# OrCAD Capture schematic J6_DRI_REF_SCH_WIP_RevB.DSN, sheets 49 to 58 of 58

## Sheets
49 SH52 - BD POWER 3V3 SWITCHED: size B; rev: A
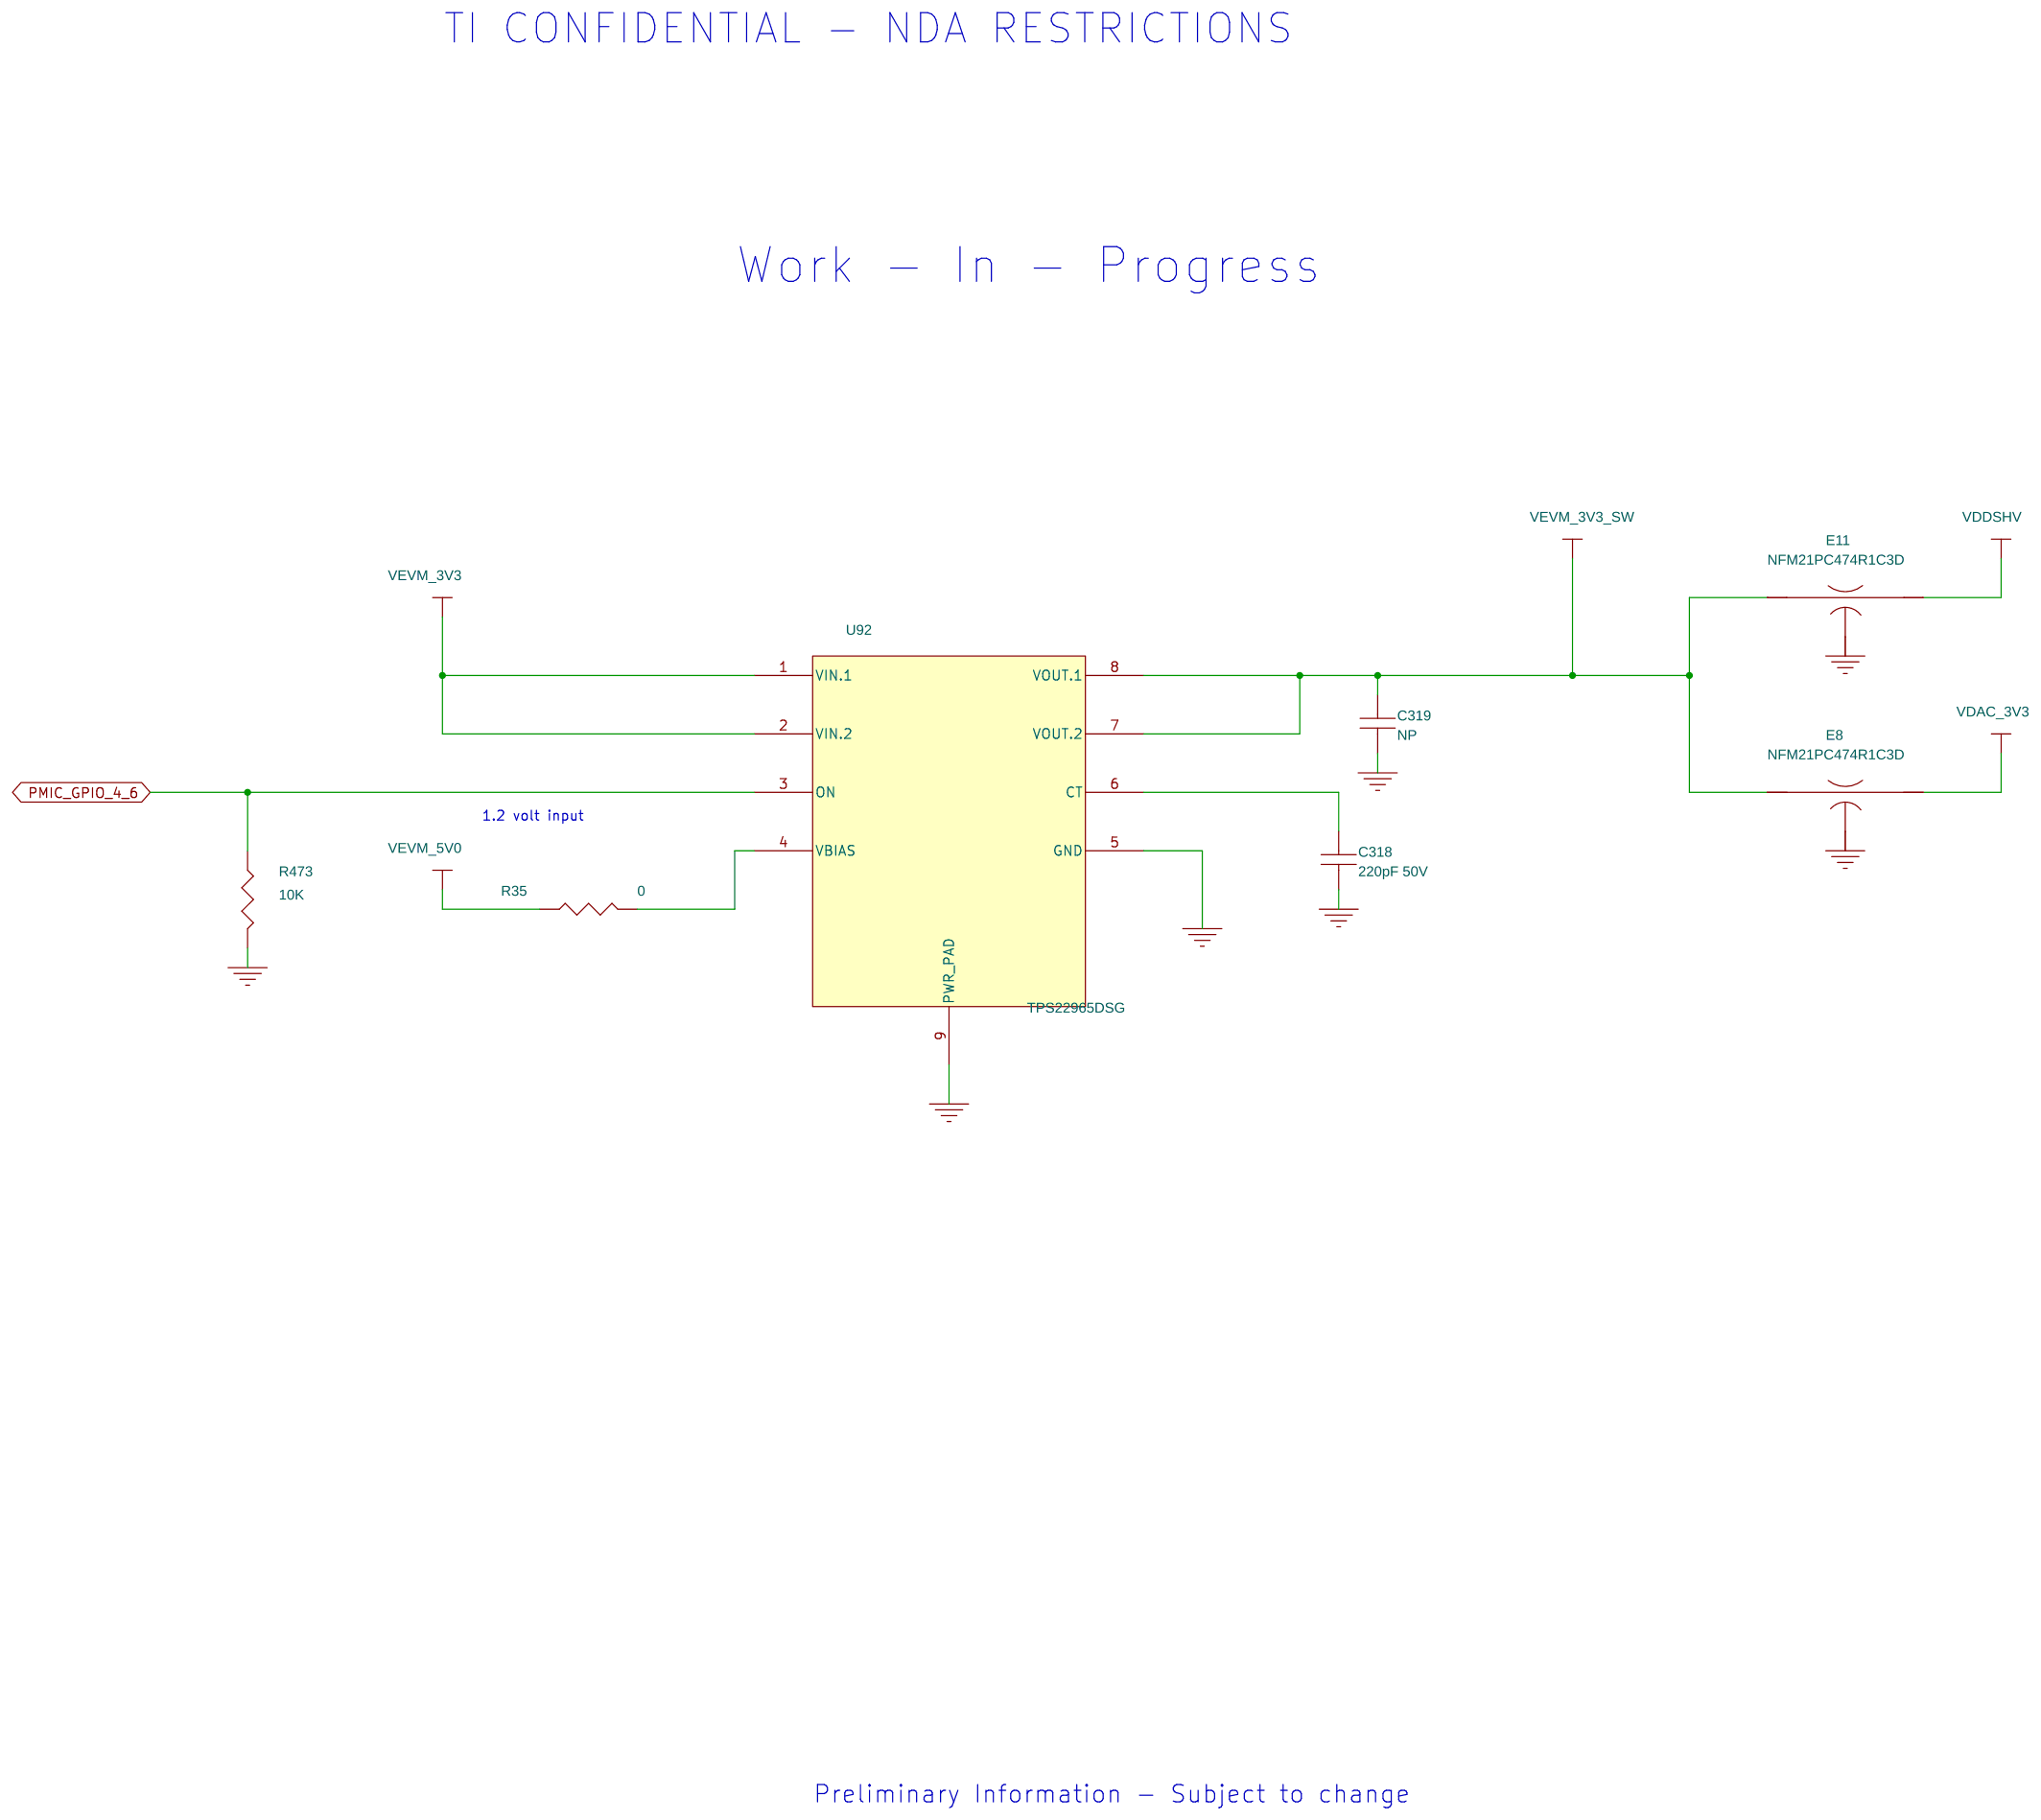
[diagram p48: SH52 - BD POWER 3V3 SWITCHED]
50 SH53 - BD POWER VTT DDR3 TERM: size B; rev: A
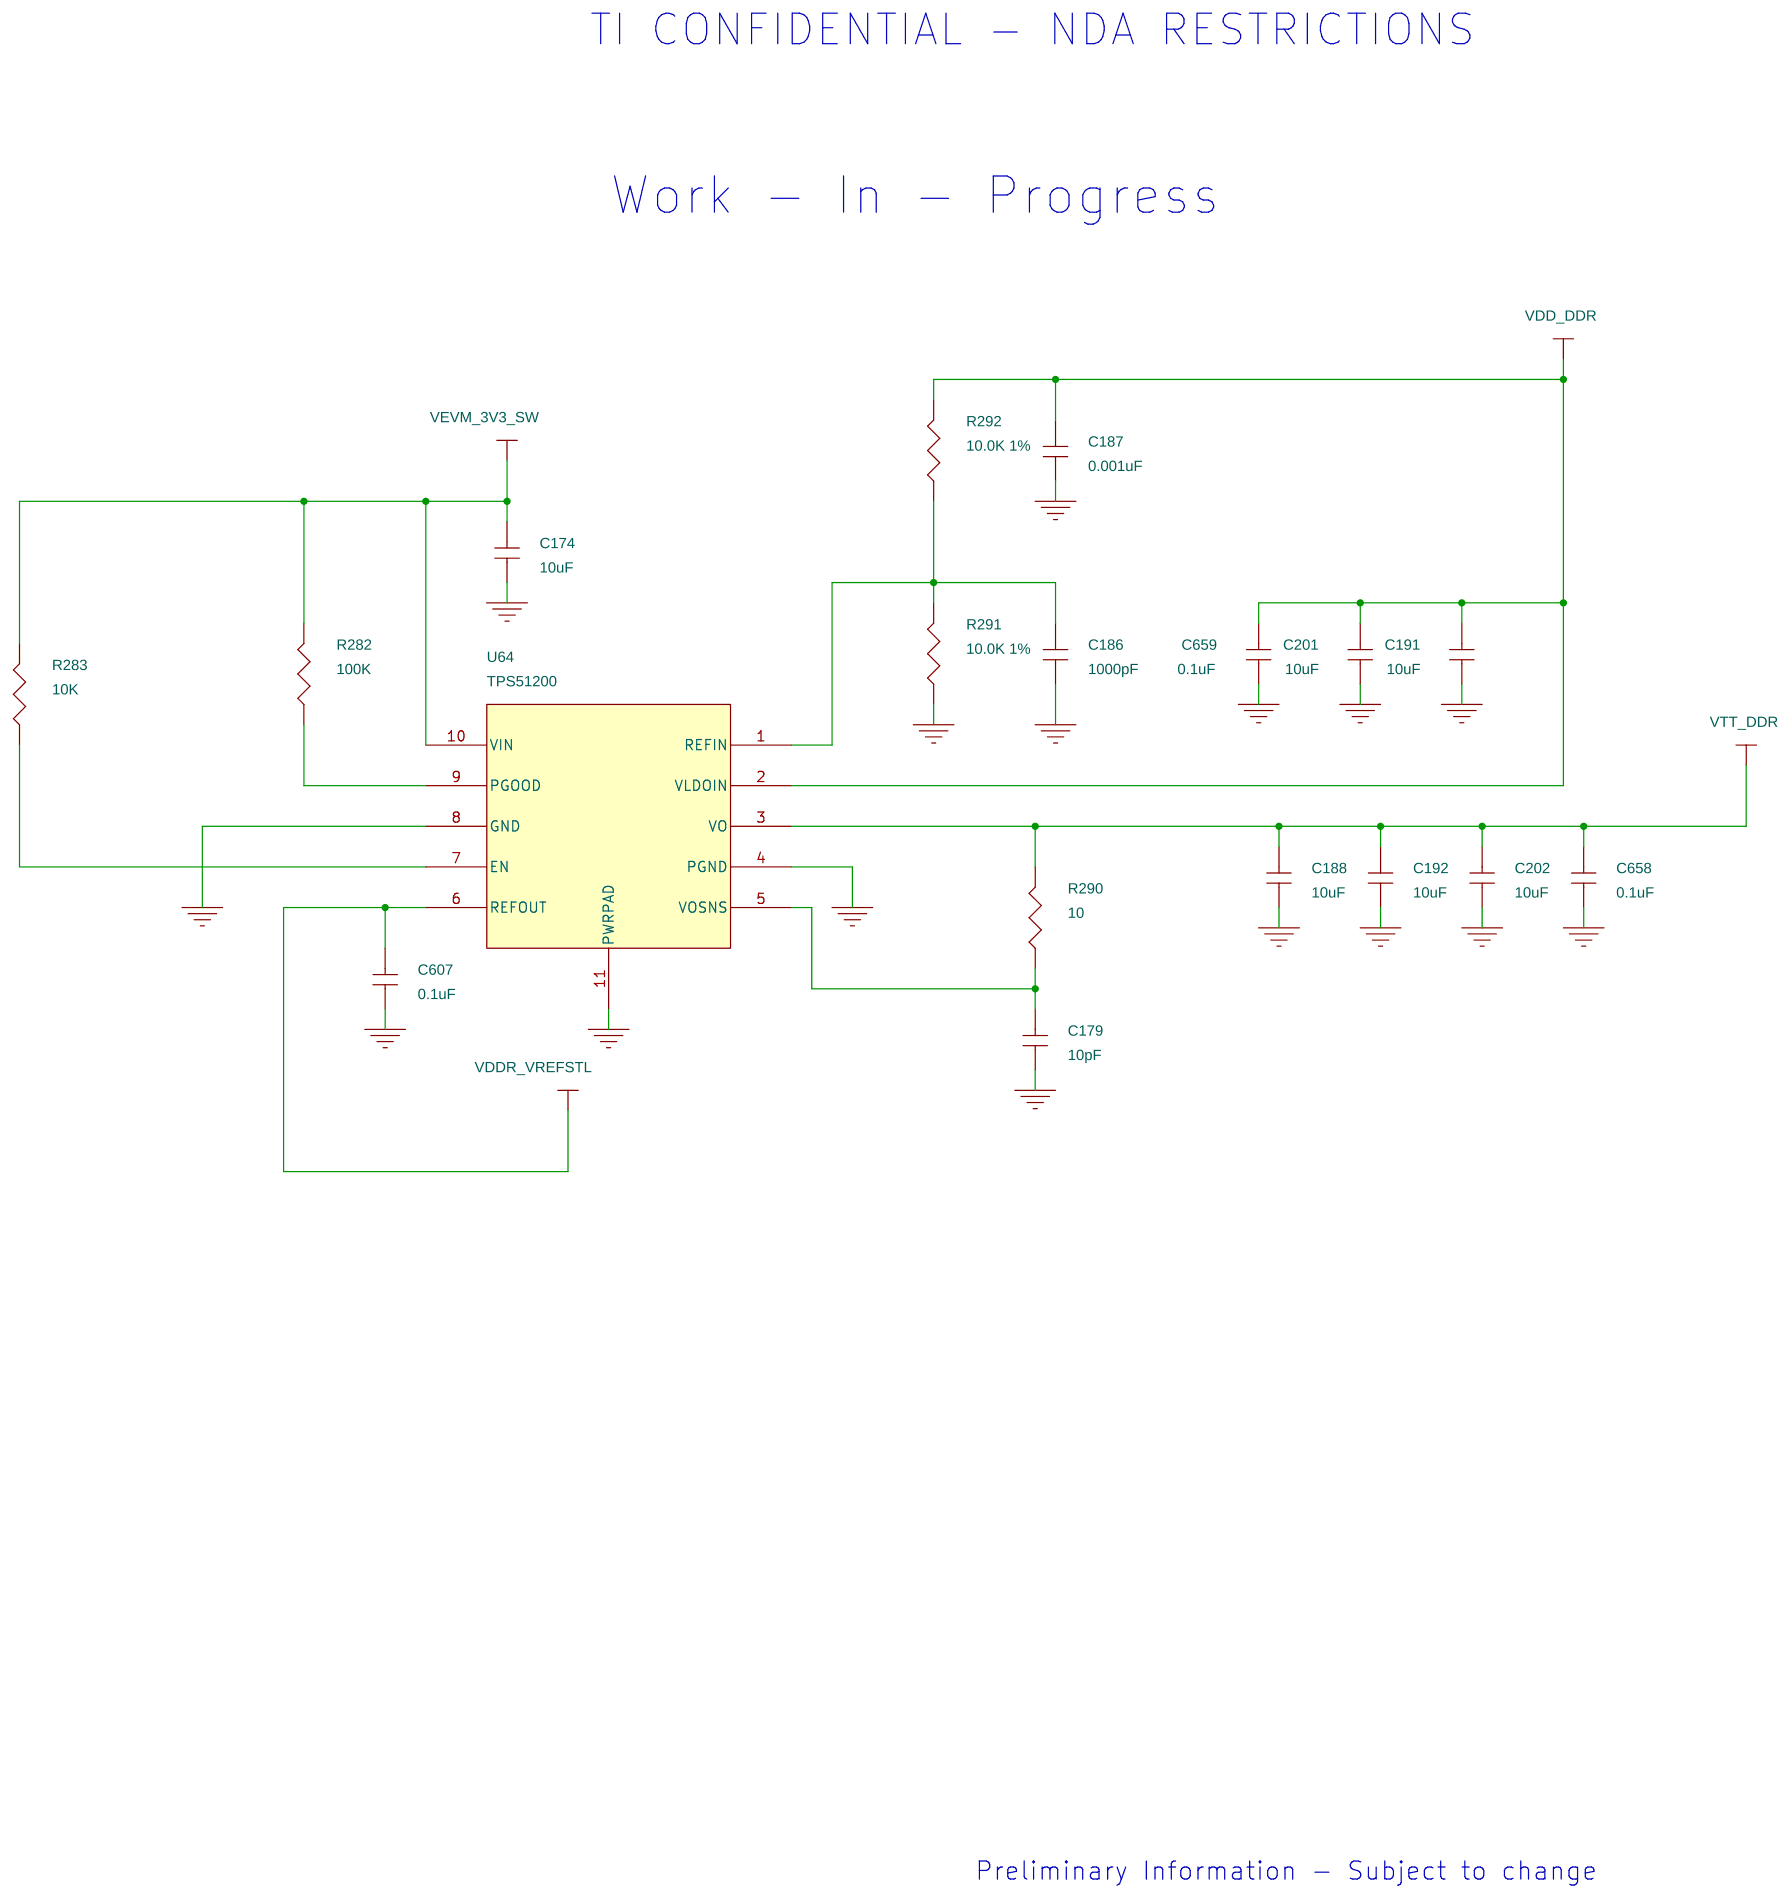
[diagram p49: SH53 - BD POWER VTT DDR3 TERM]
51 SH54 - BD POWER 1V35 DDR3 CORE: size B; rev: A
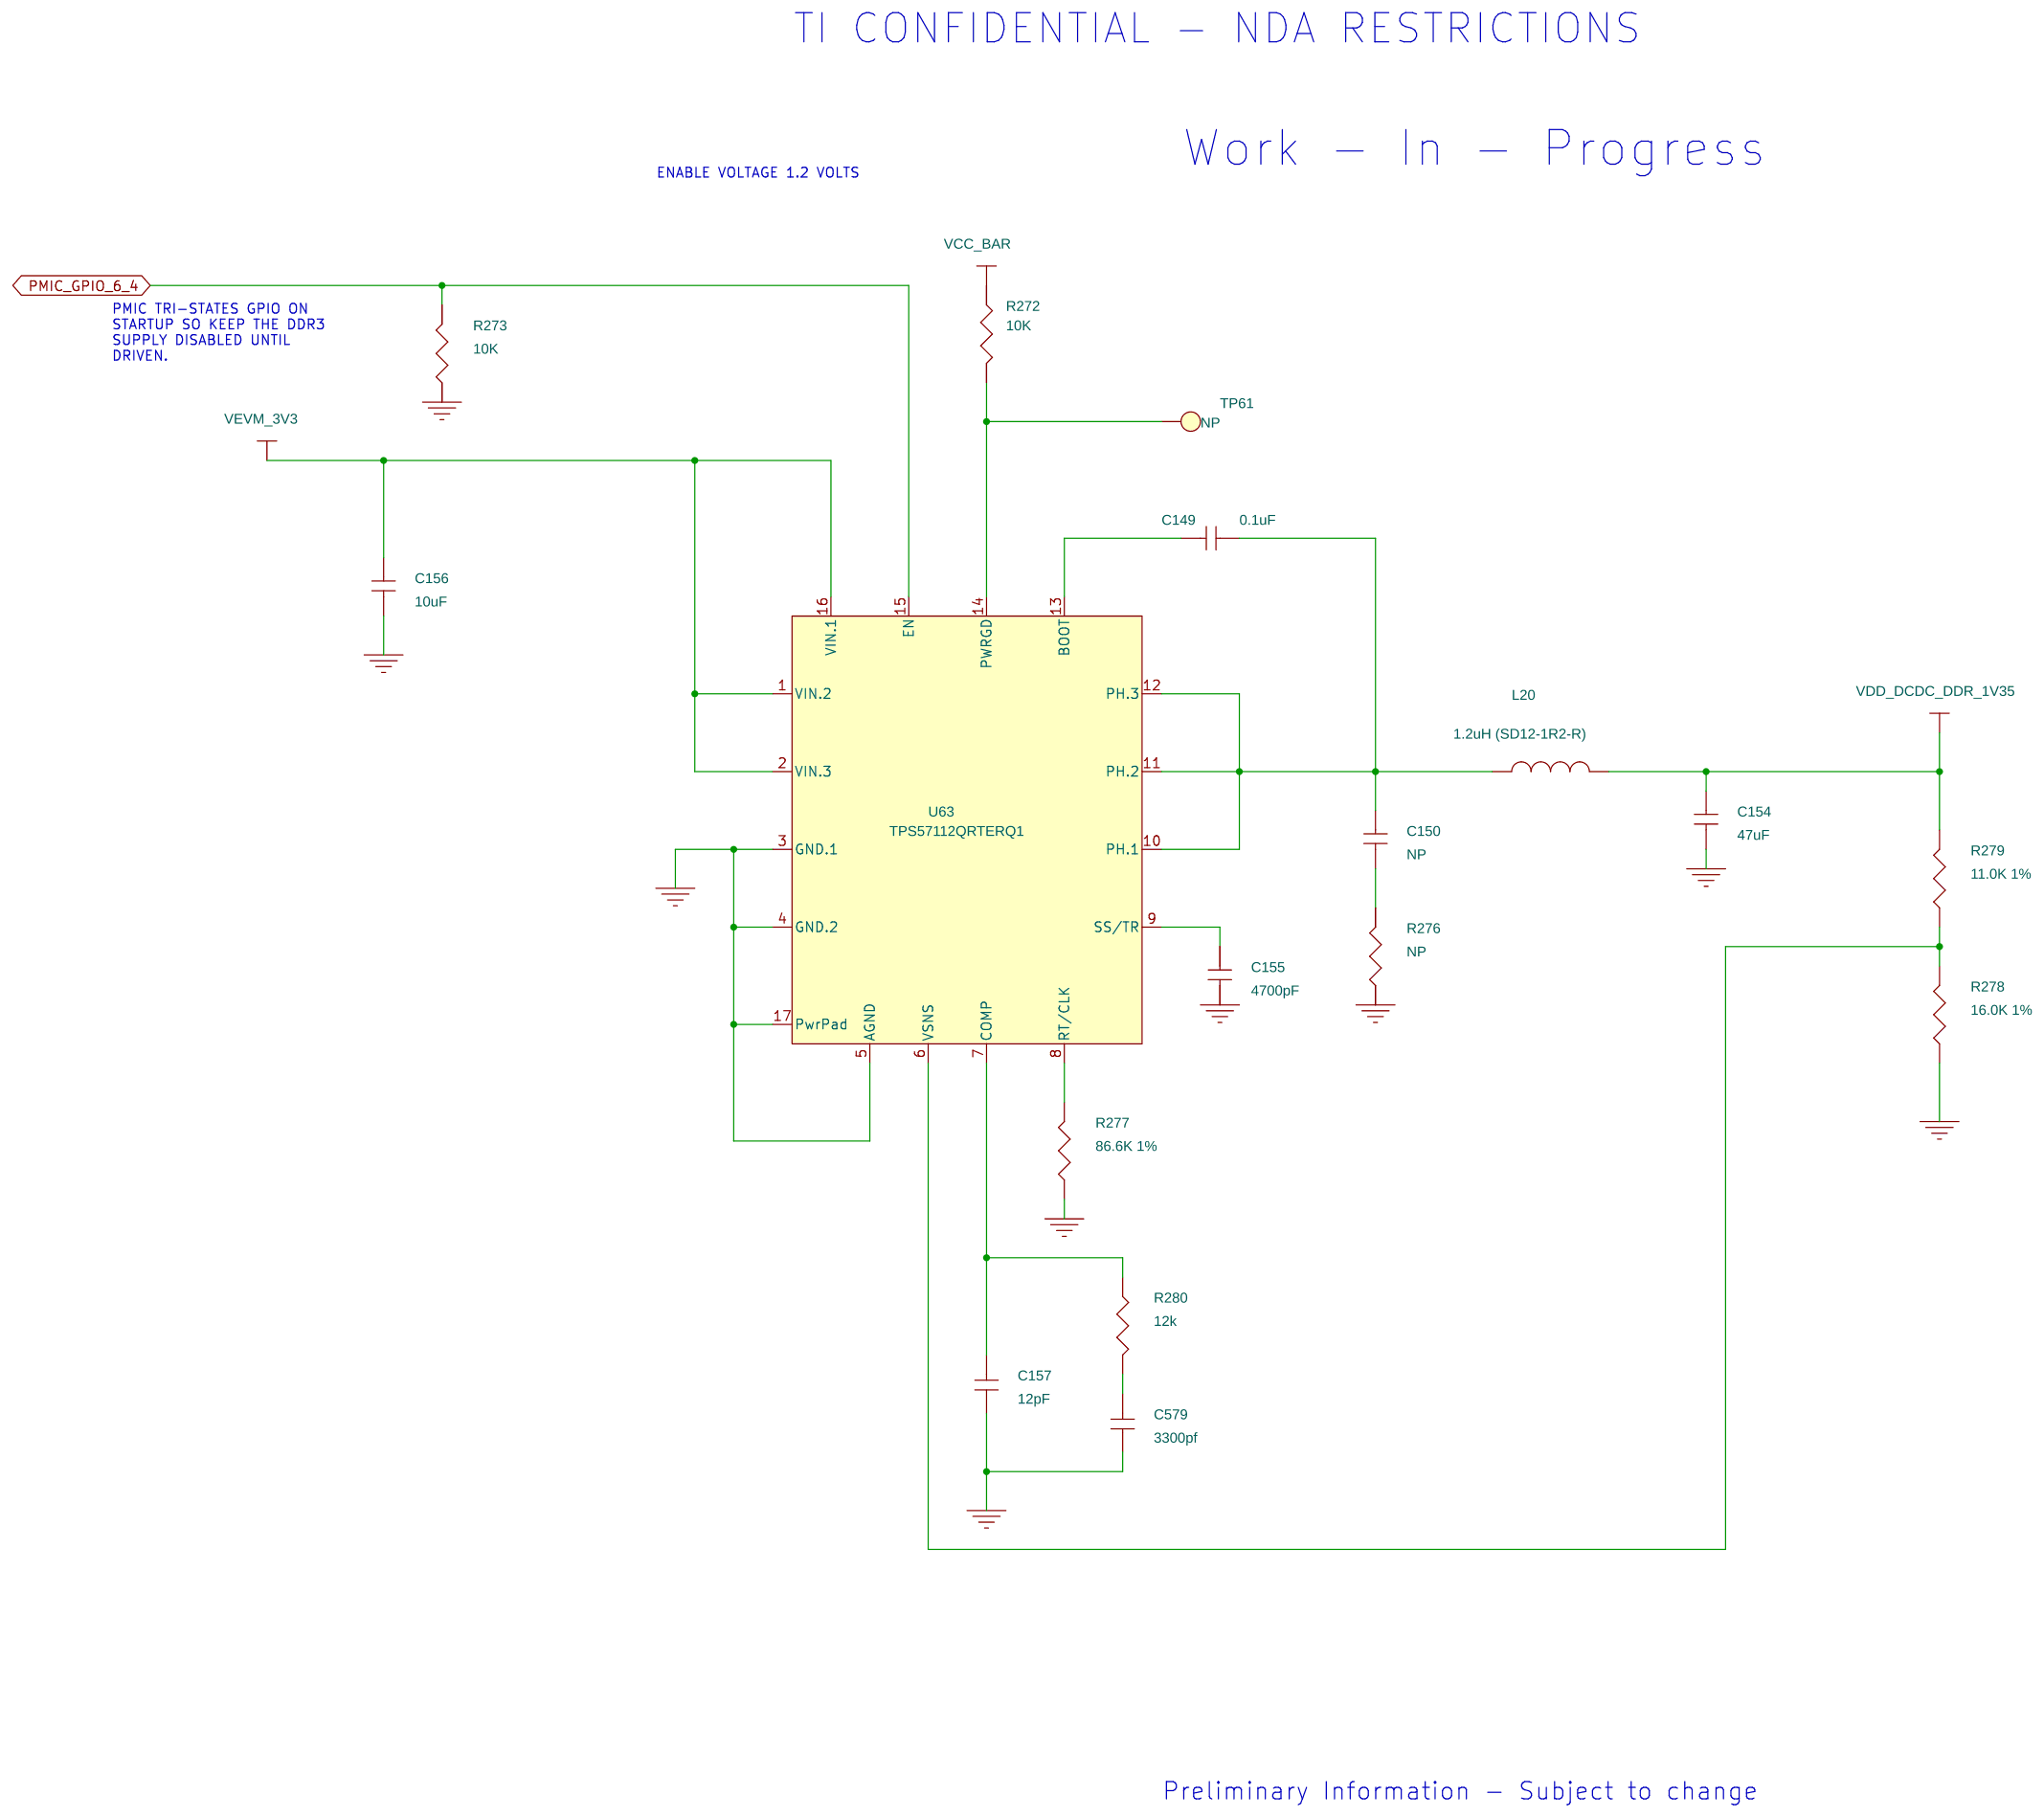
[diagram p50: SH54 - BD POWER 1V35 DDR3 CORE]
52 SH55 - BD EEPROM TEMP IPOD: size B; rev: A
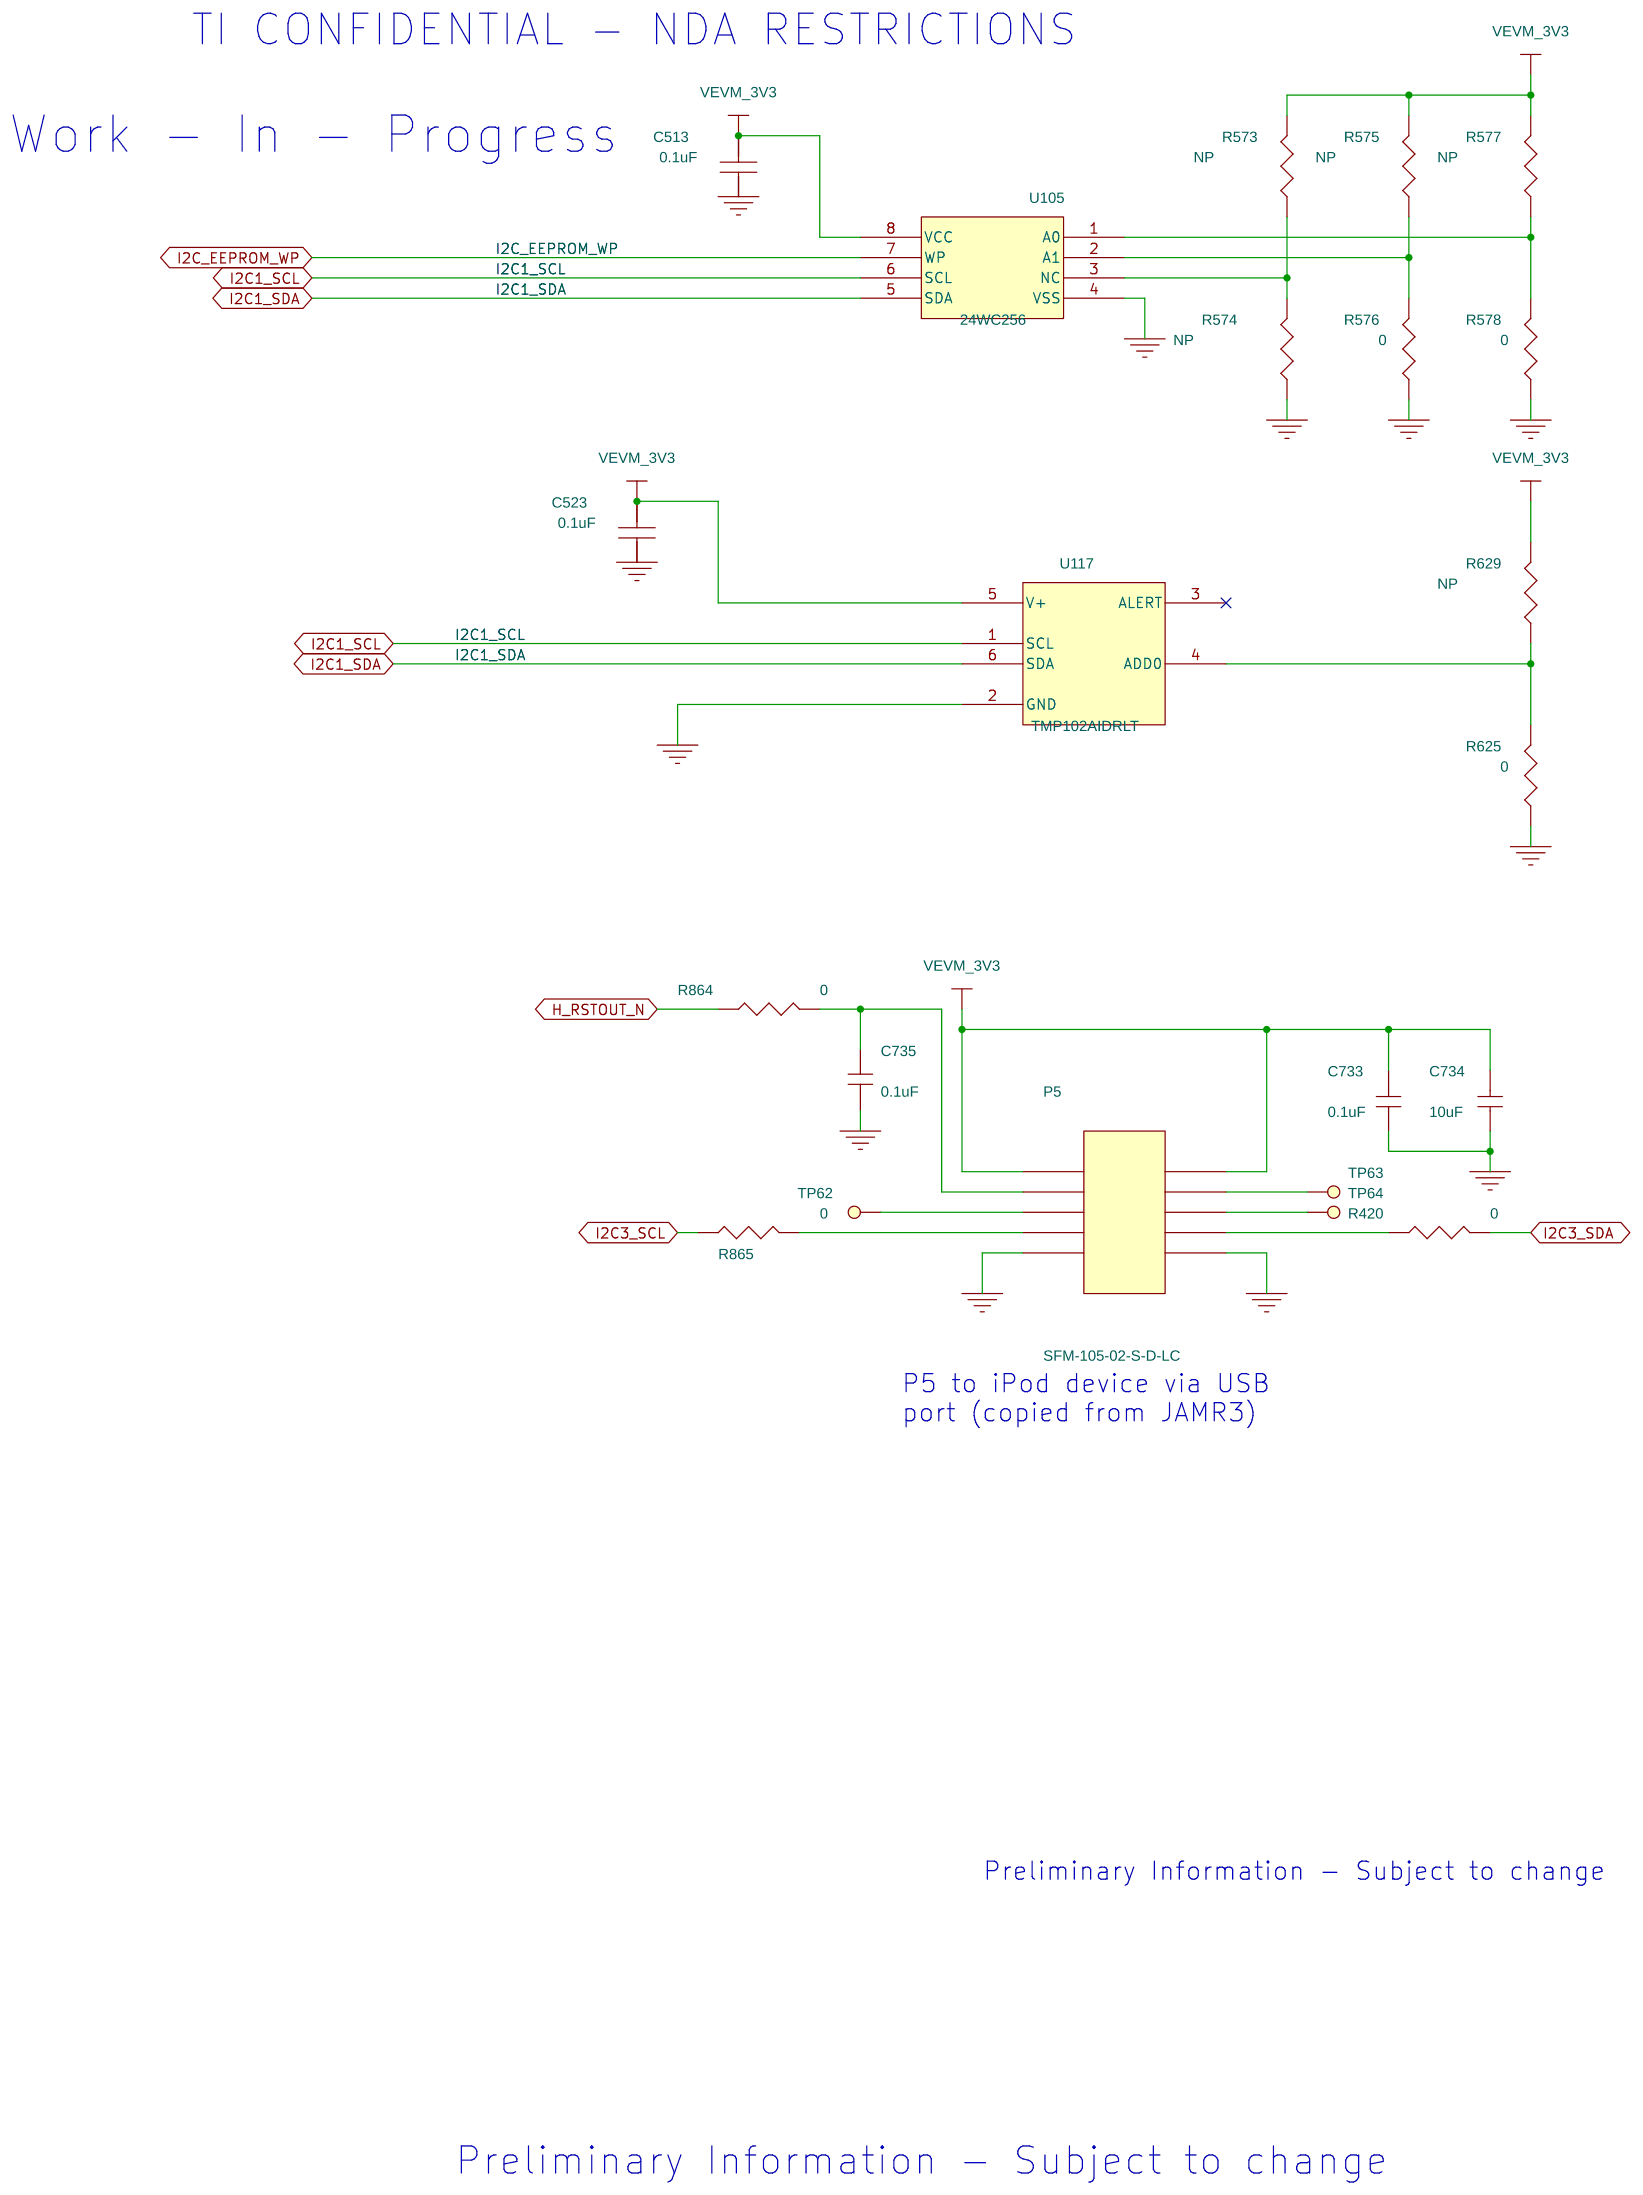
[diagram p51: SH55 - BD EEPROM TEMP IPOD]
53 SH90 - PCB Design Notes: rev: A
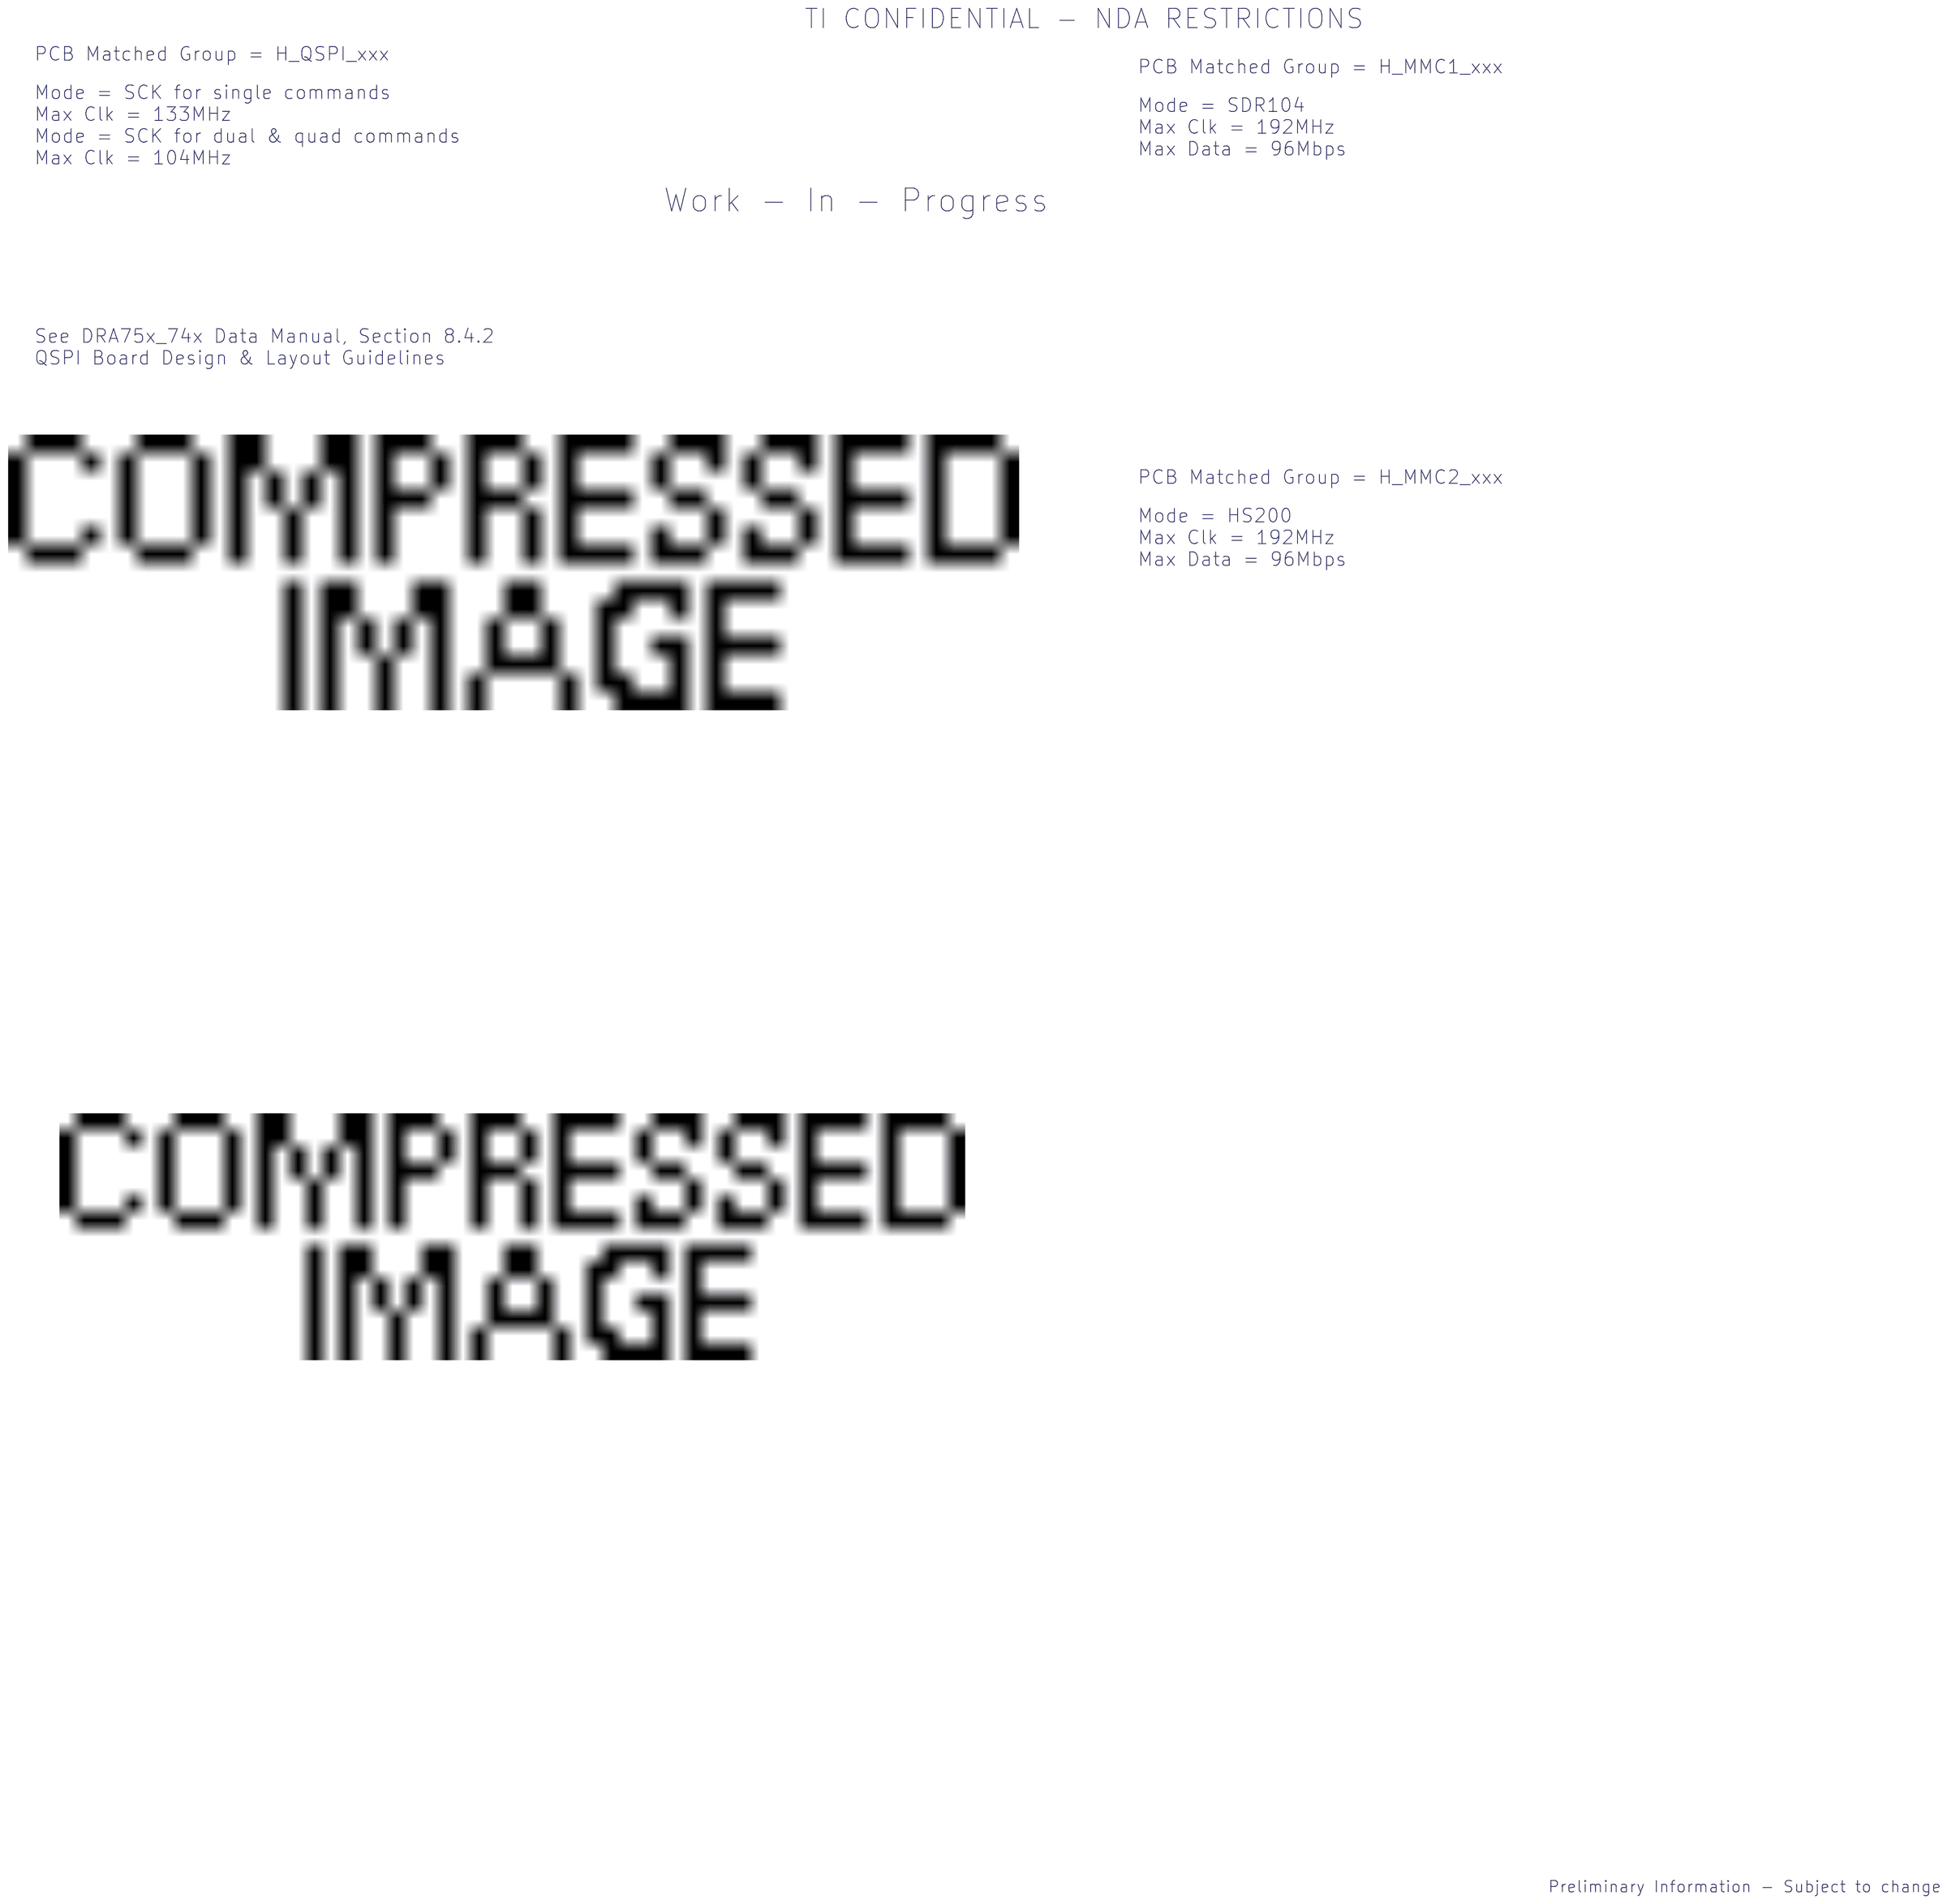
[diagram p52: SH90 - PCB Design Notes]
54 SH99 - REV HISTORY: rev: A
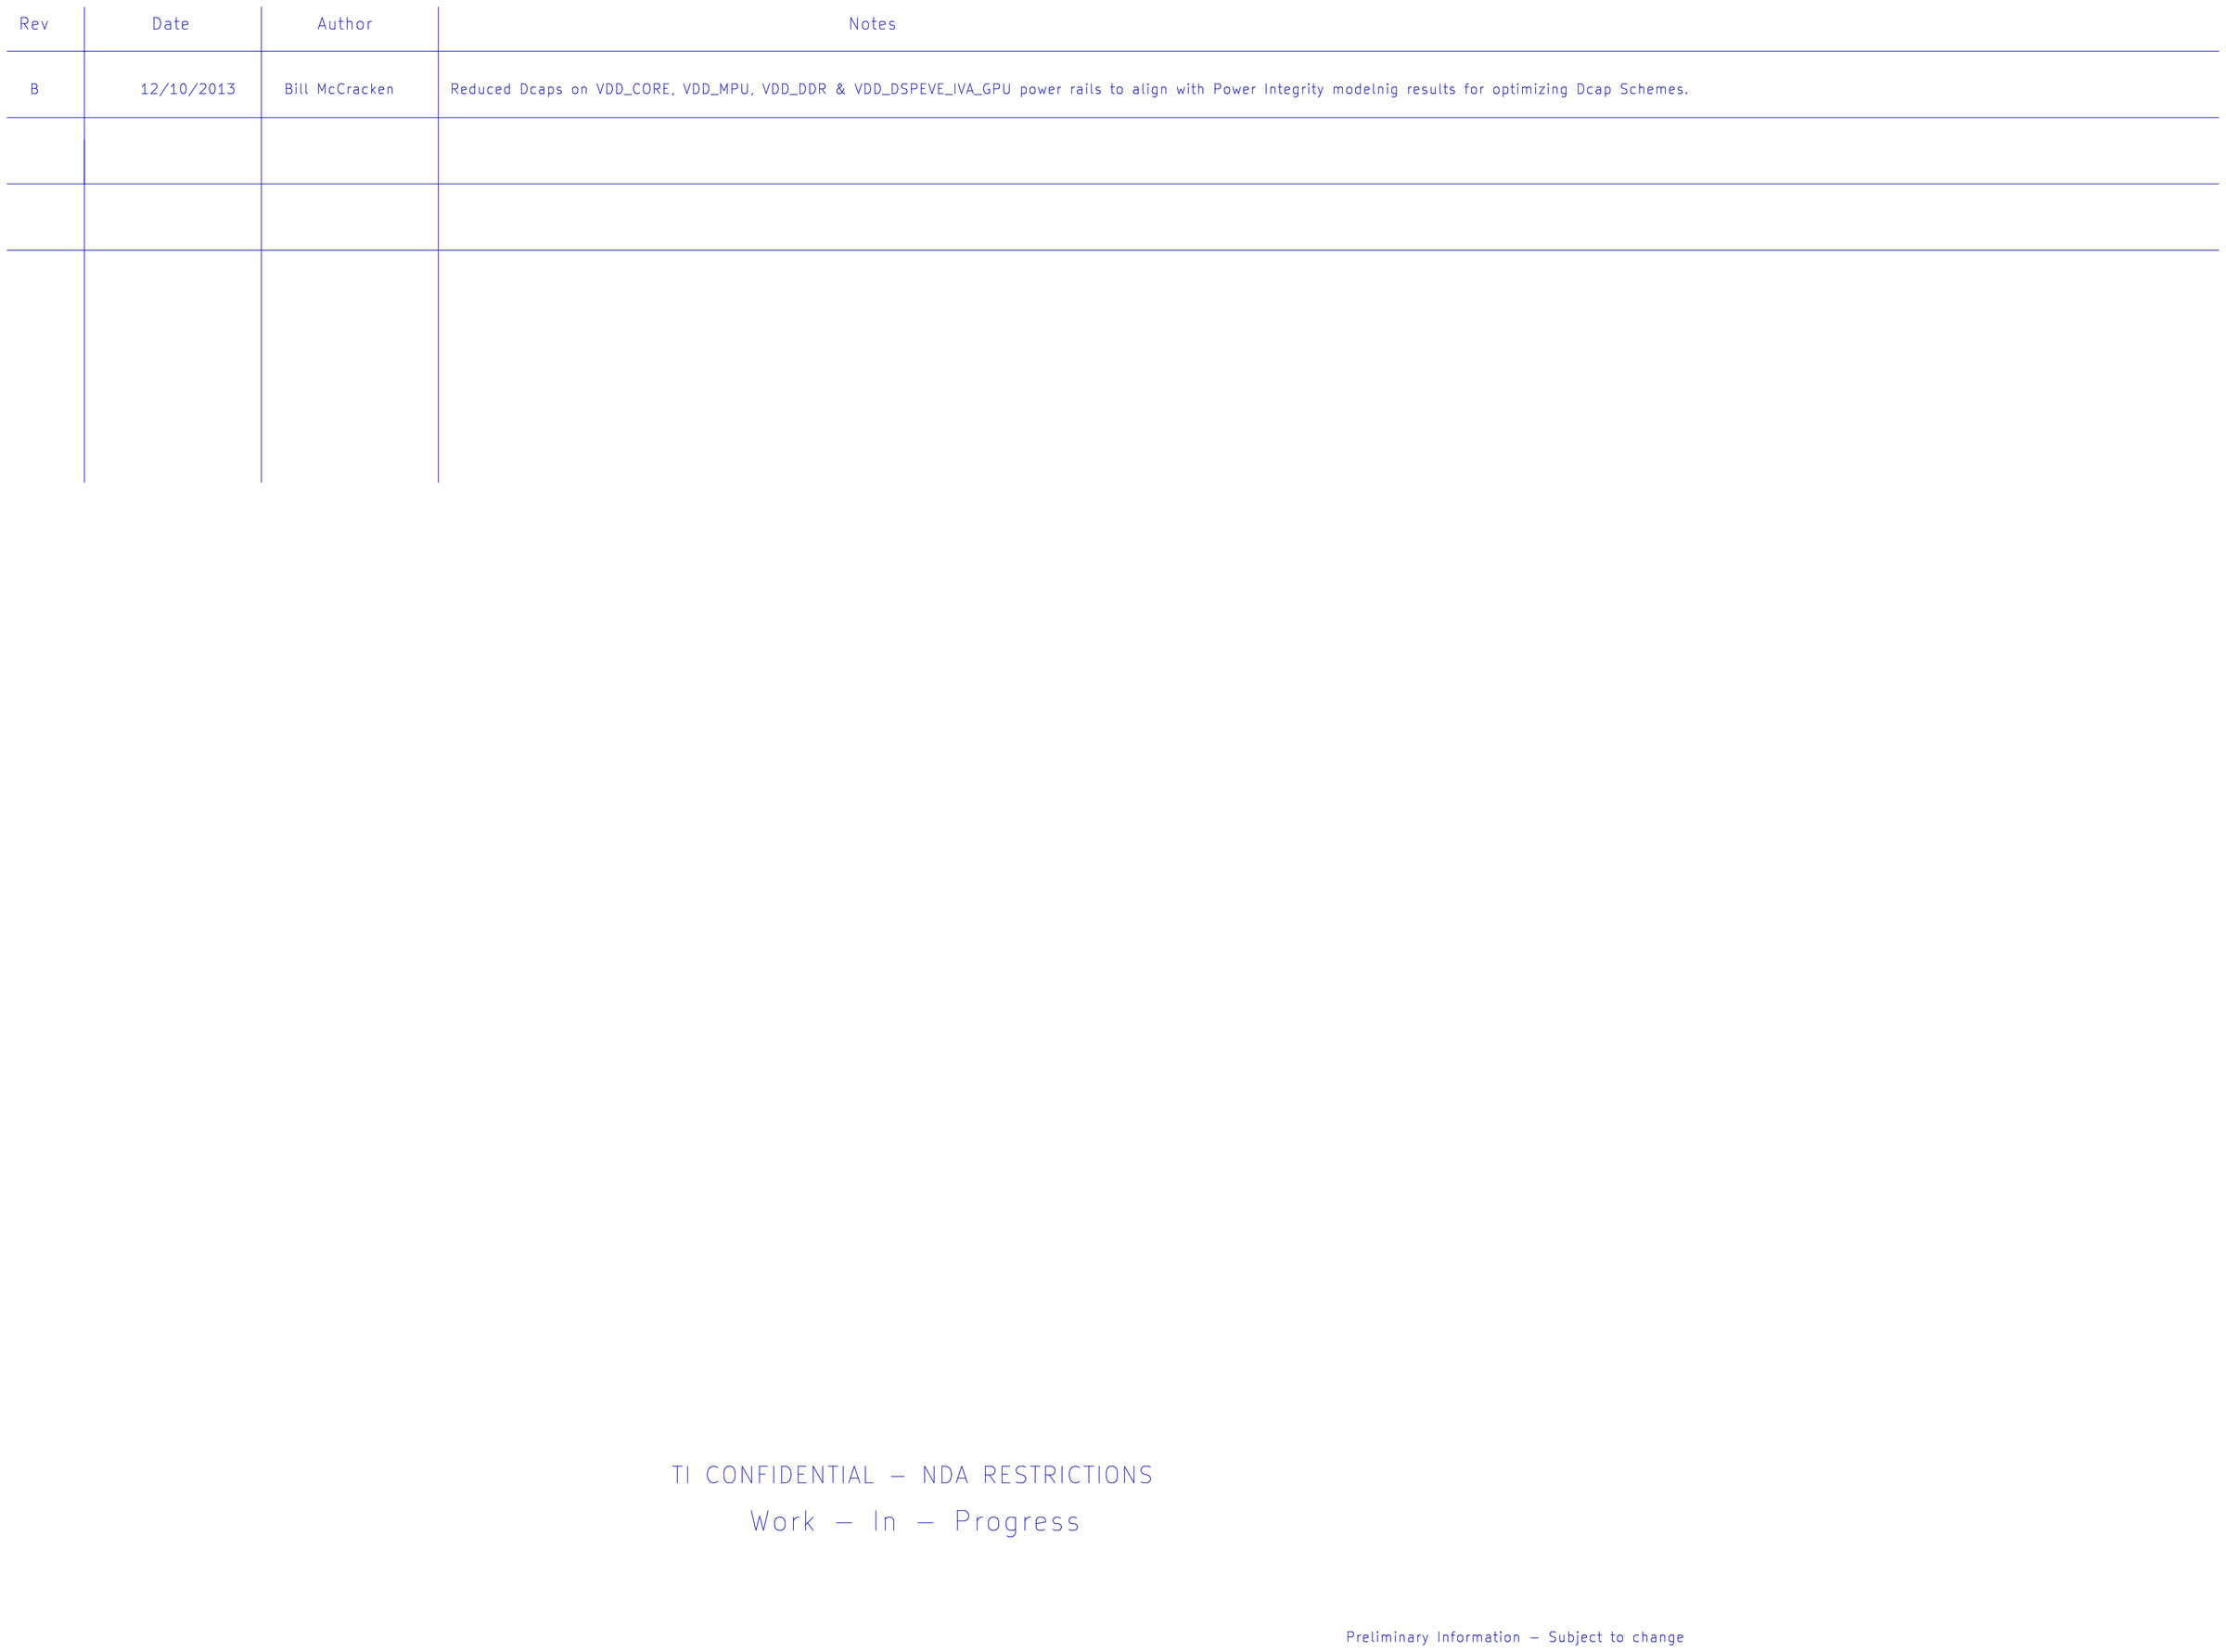
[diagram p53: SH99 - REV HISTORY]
55 SH39 - CAN/LIN: size B; rev: A
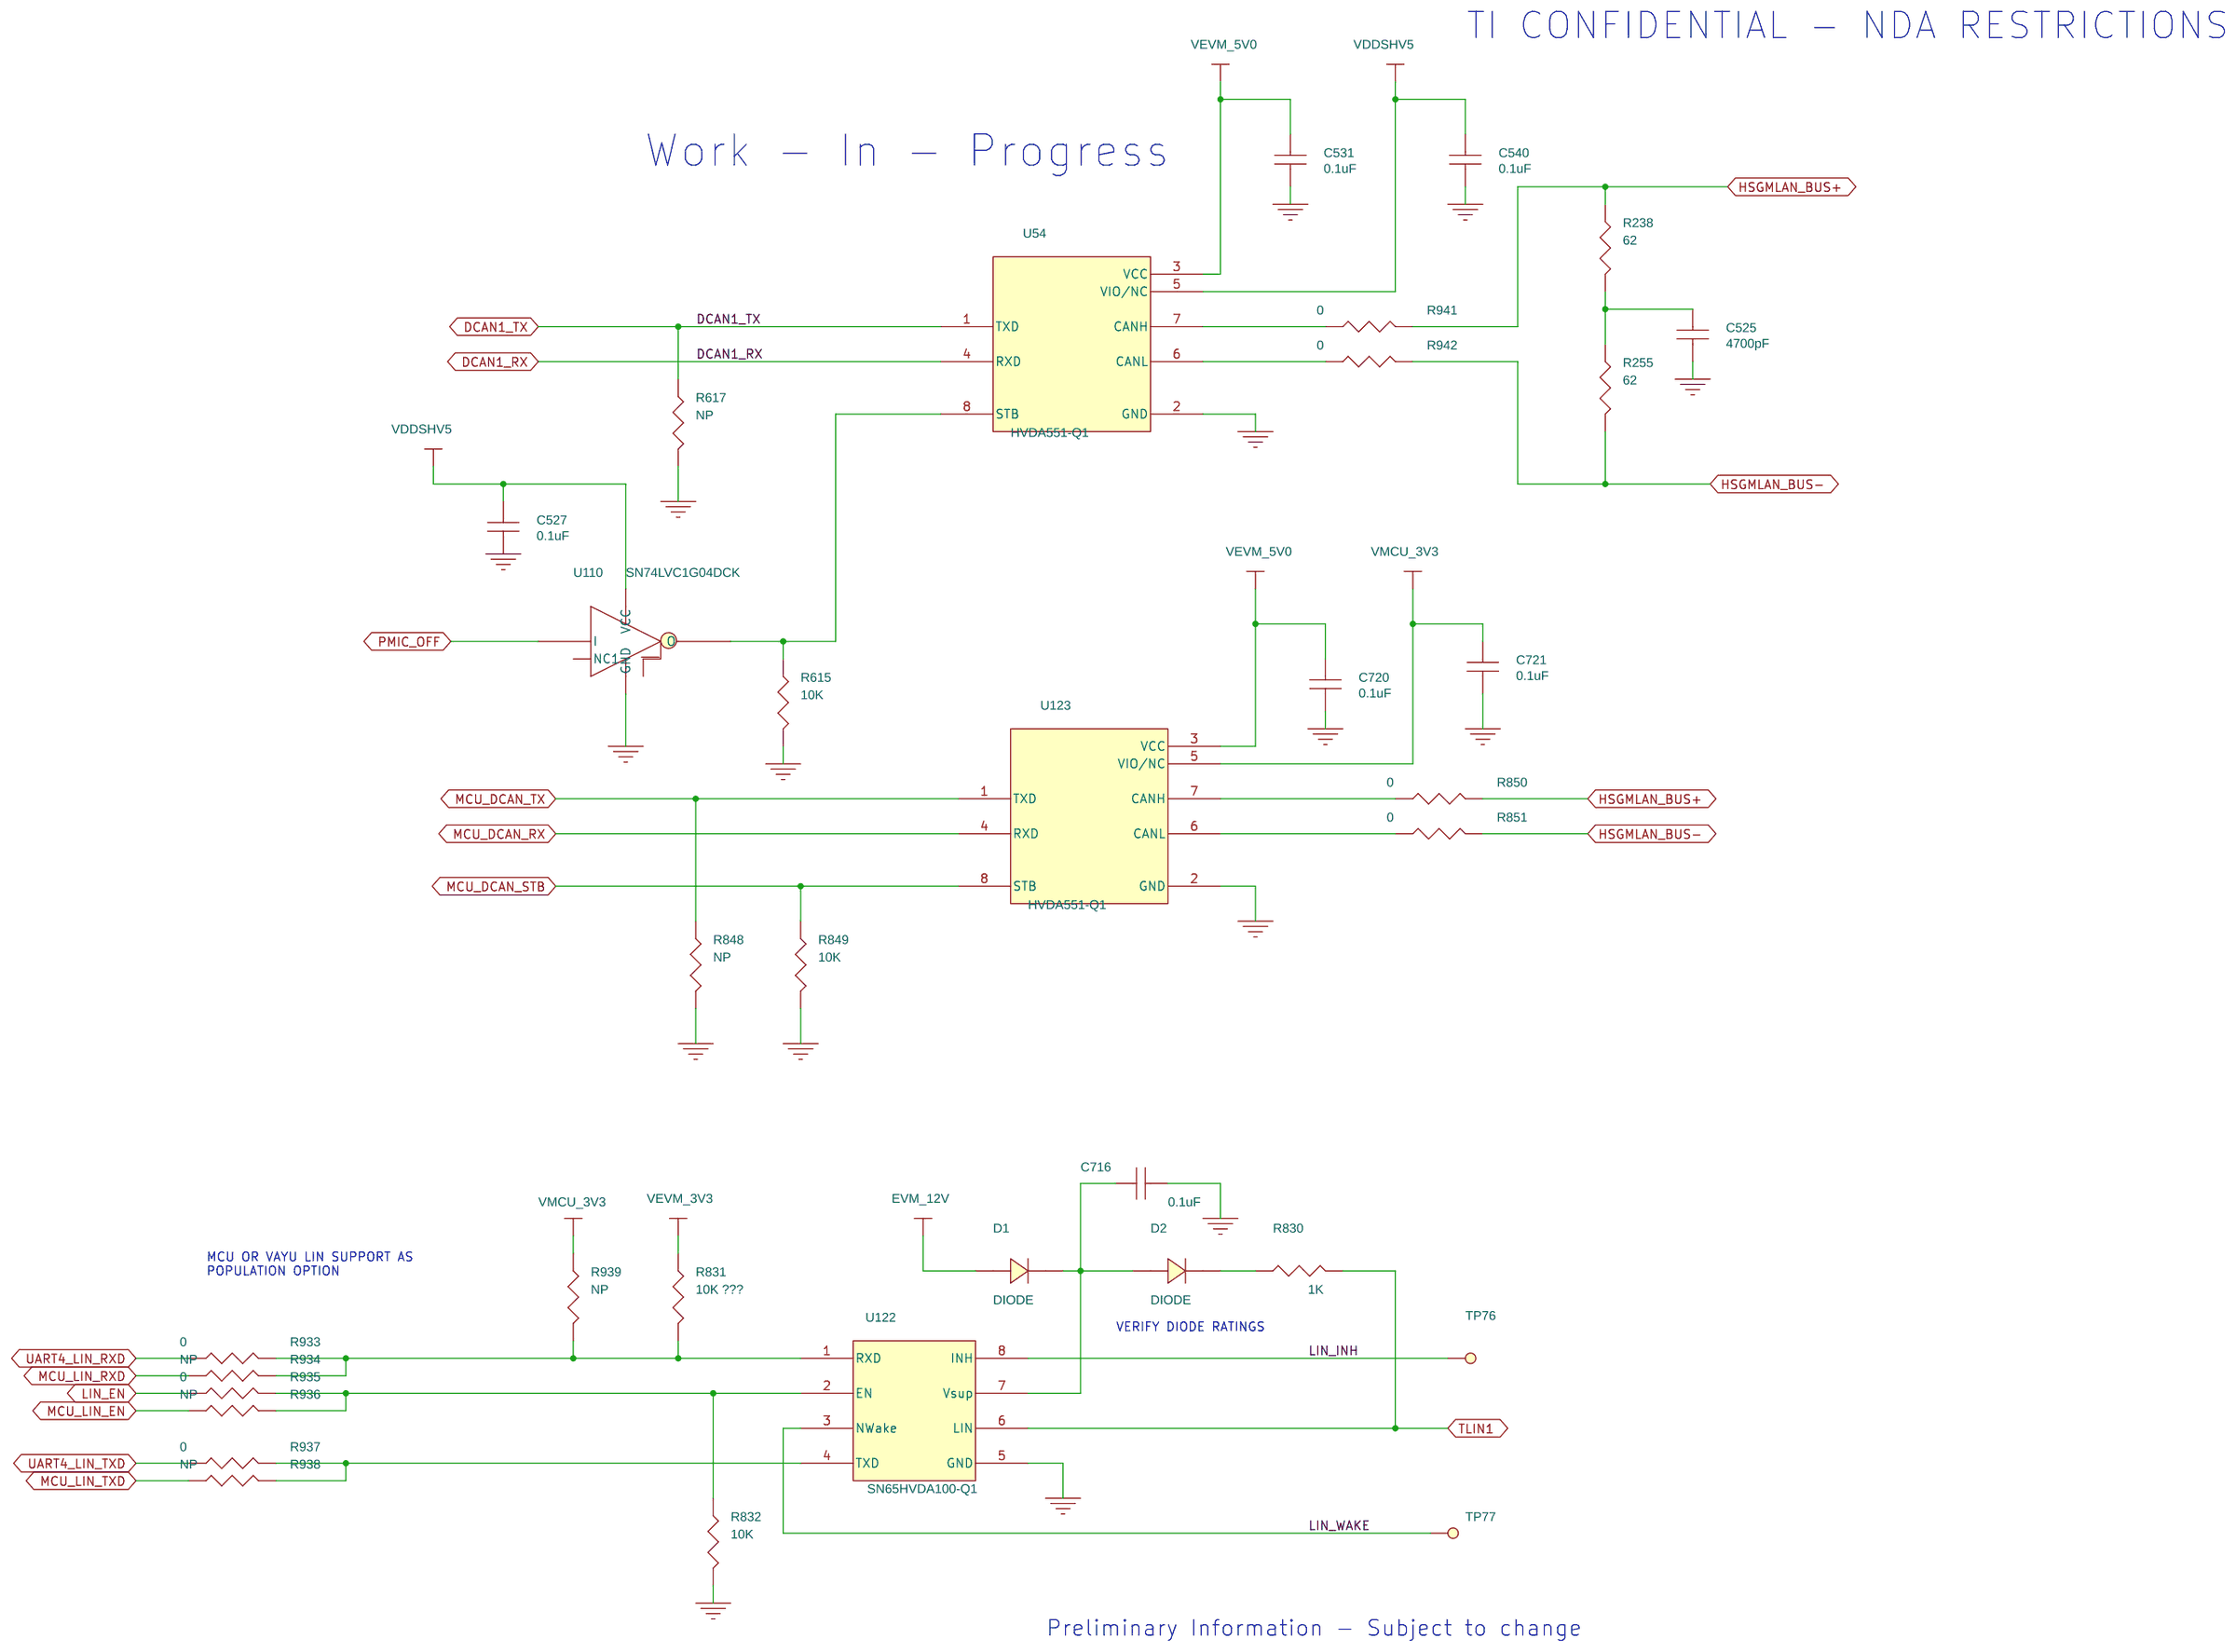
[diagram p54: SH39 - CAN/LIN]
56 SH03 - VAYU SERIAL I/O: size B; rev: A
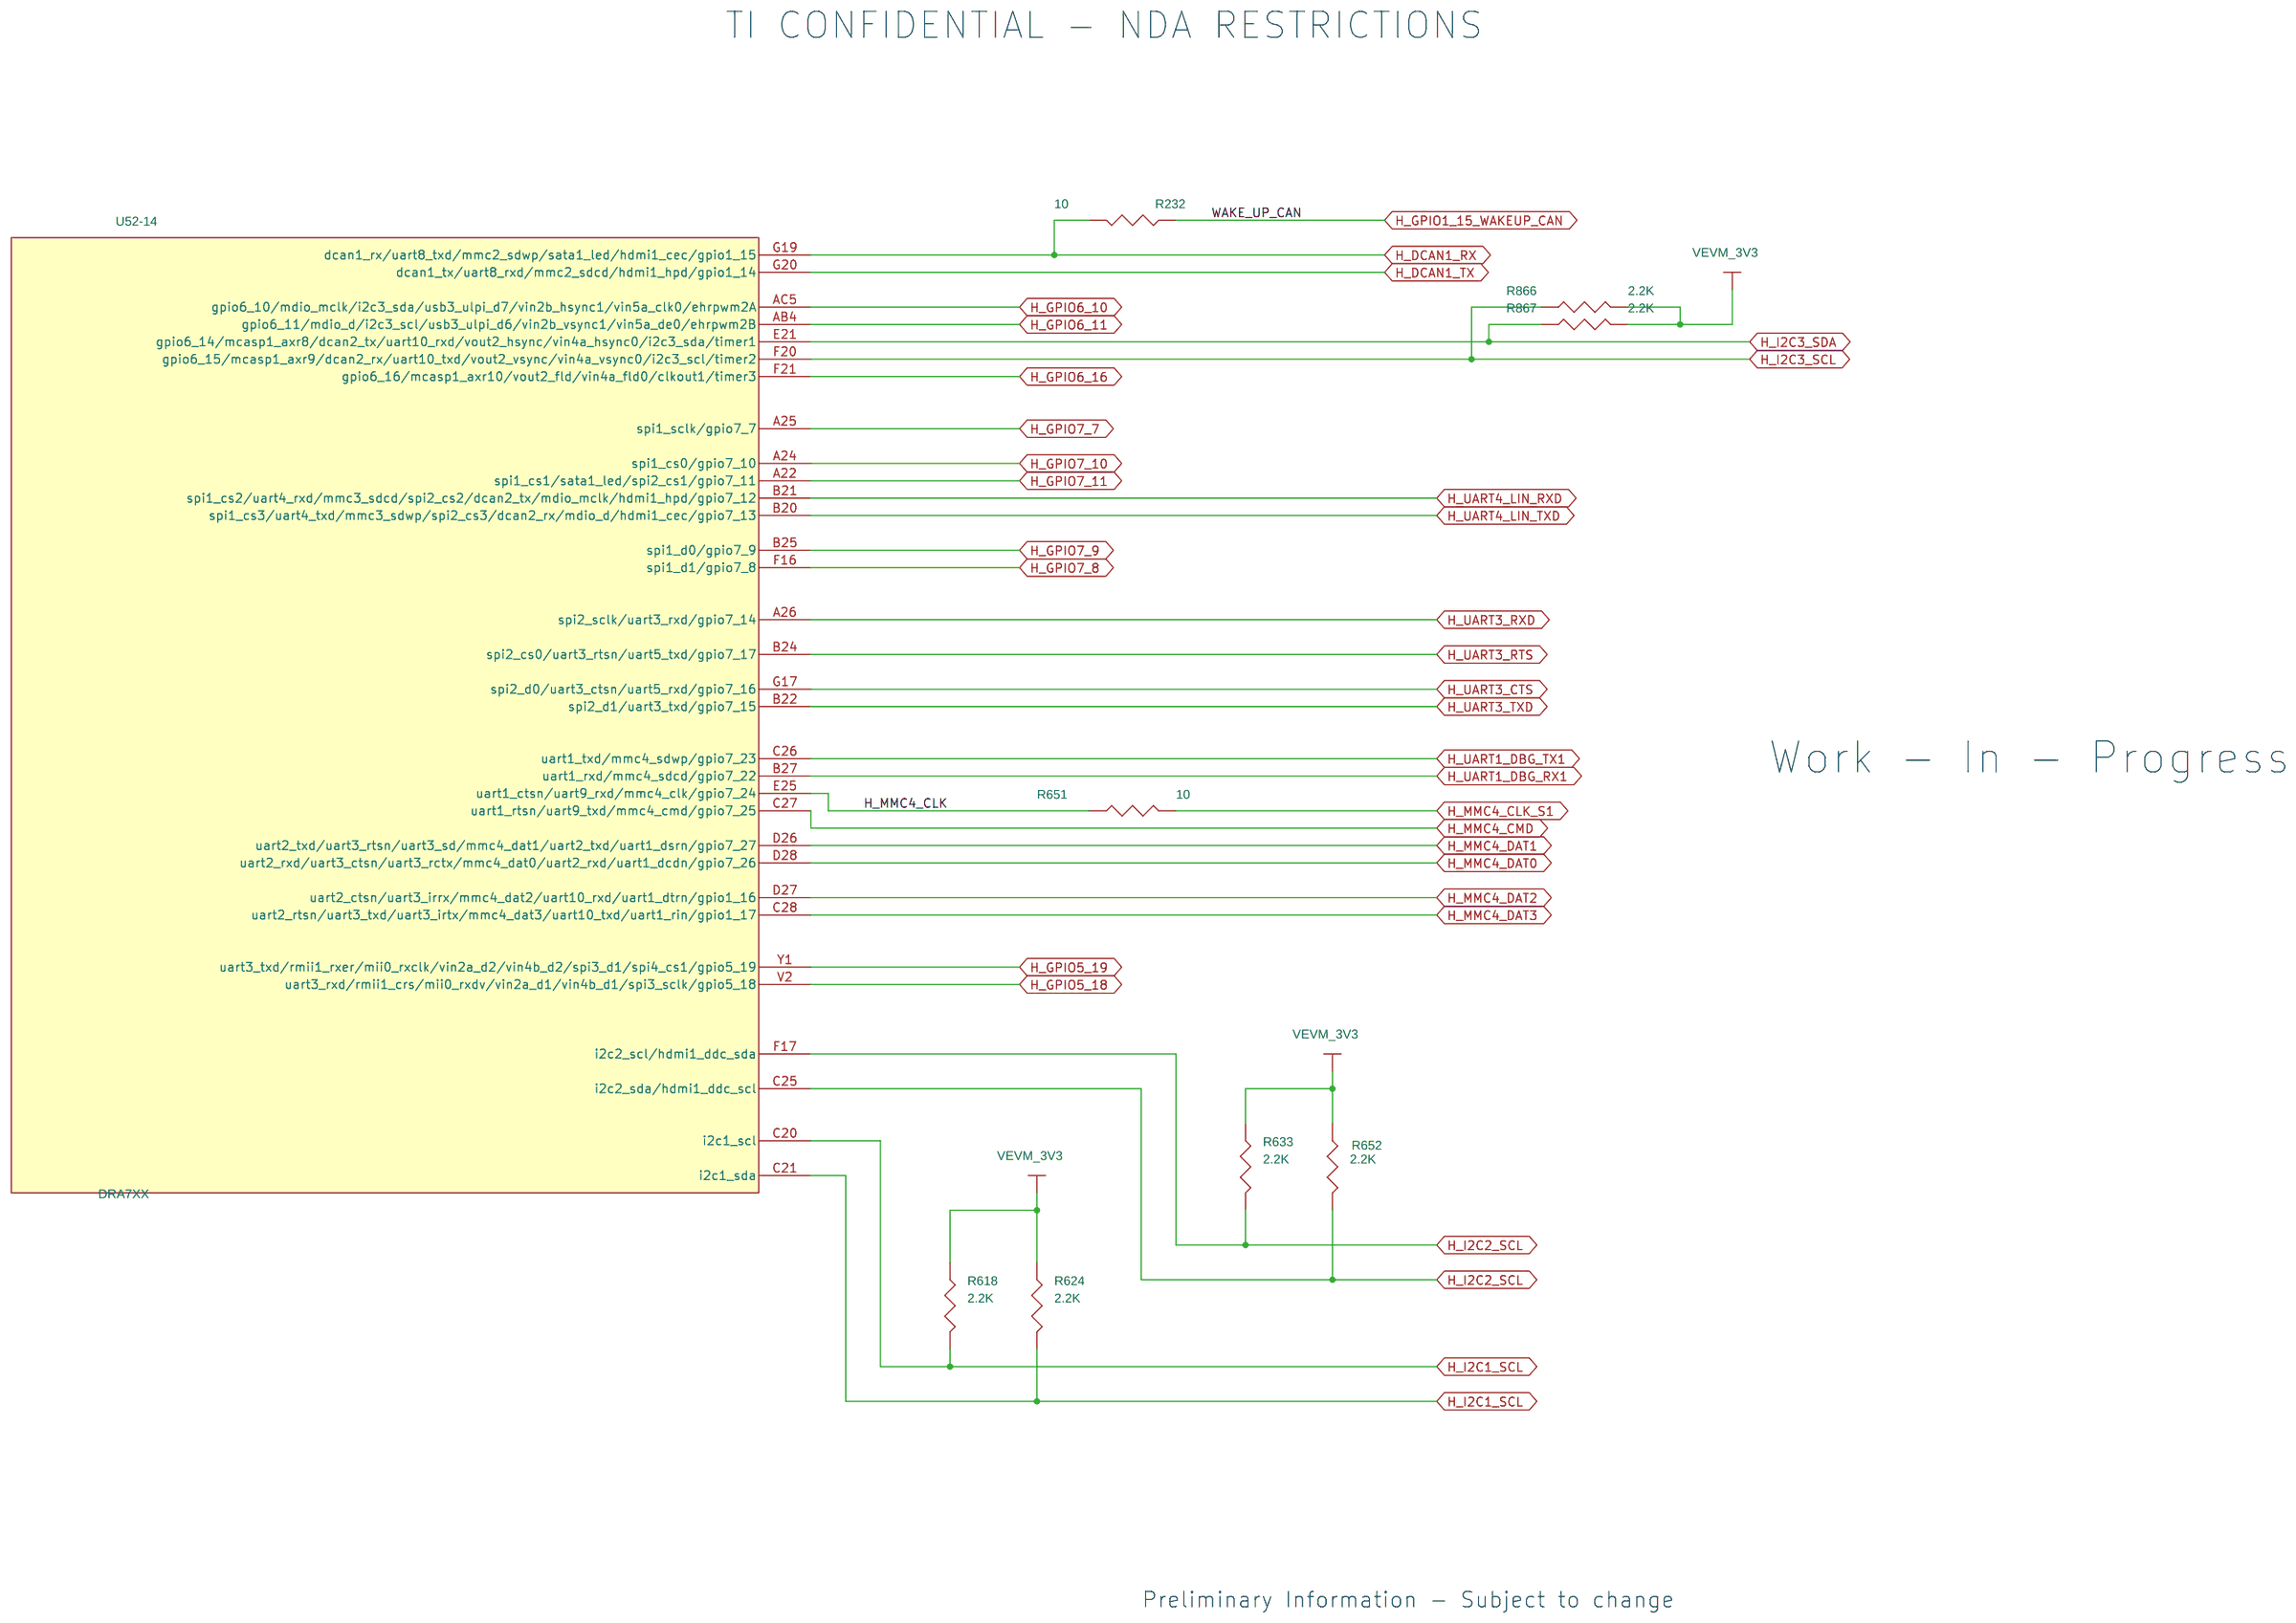
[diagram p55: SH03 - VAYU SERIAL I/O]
57 SH25 - SERIAL I/O MUX: size B; title: VAYU EVM; rev: E; note: 516582-0001
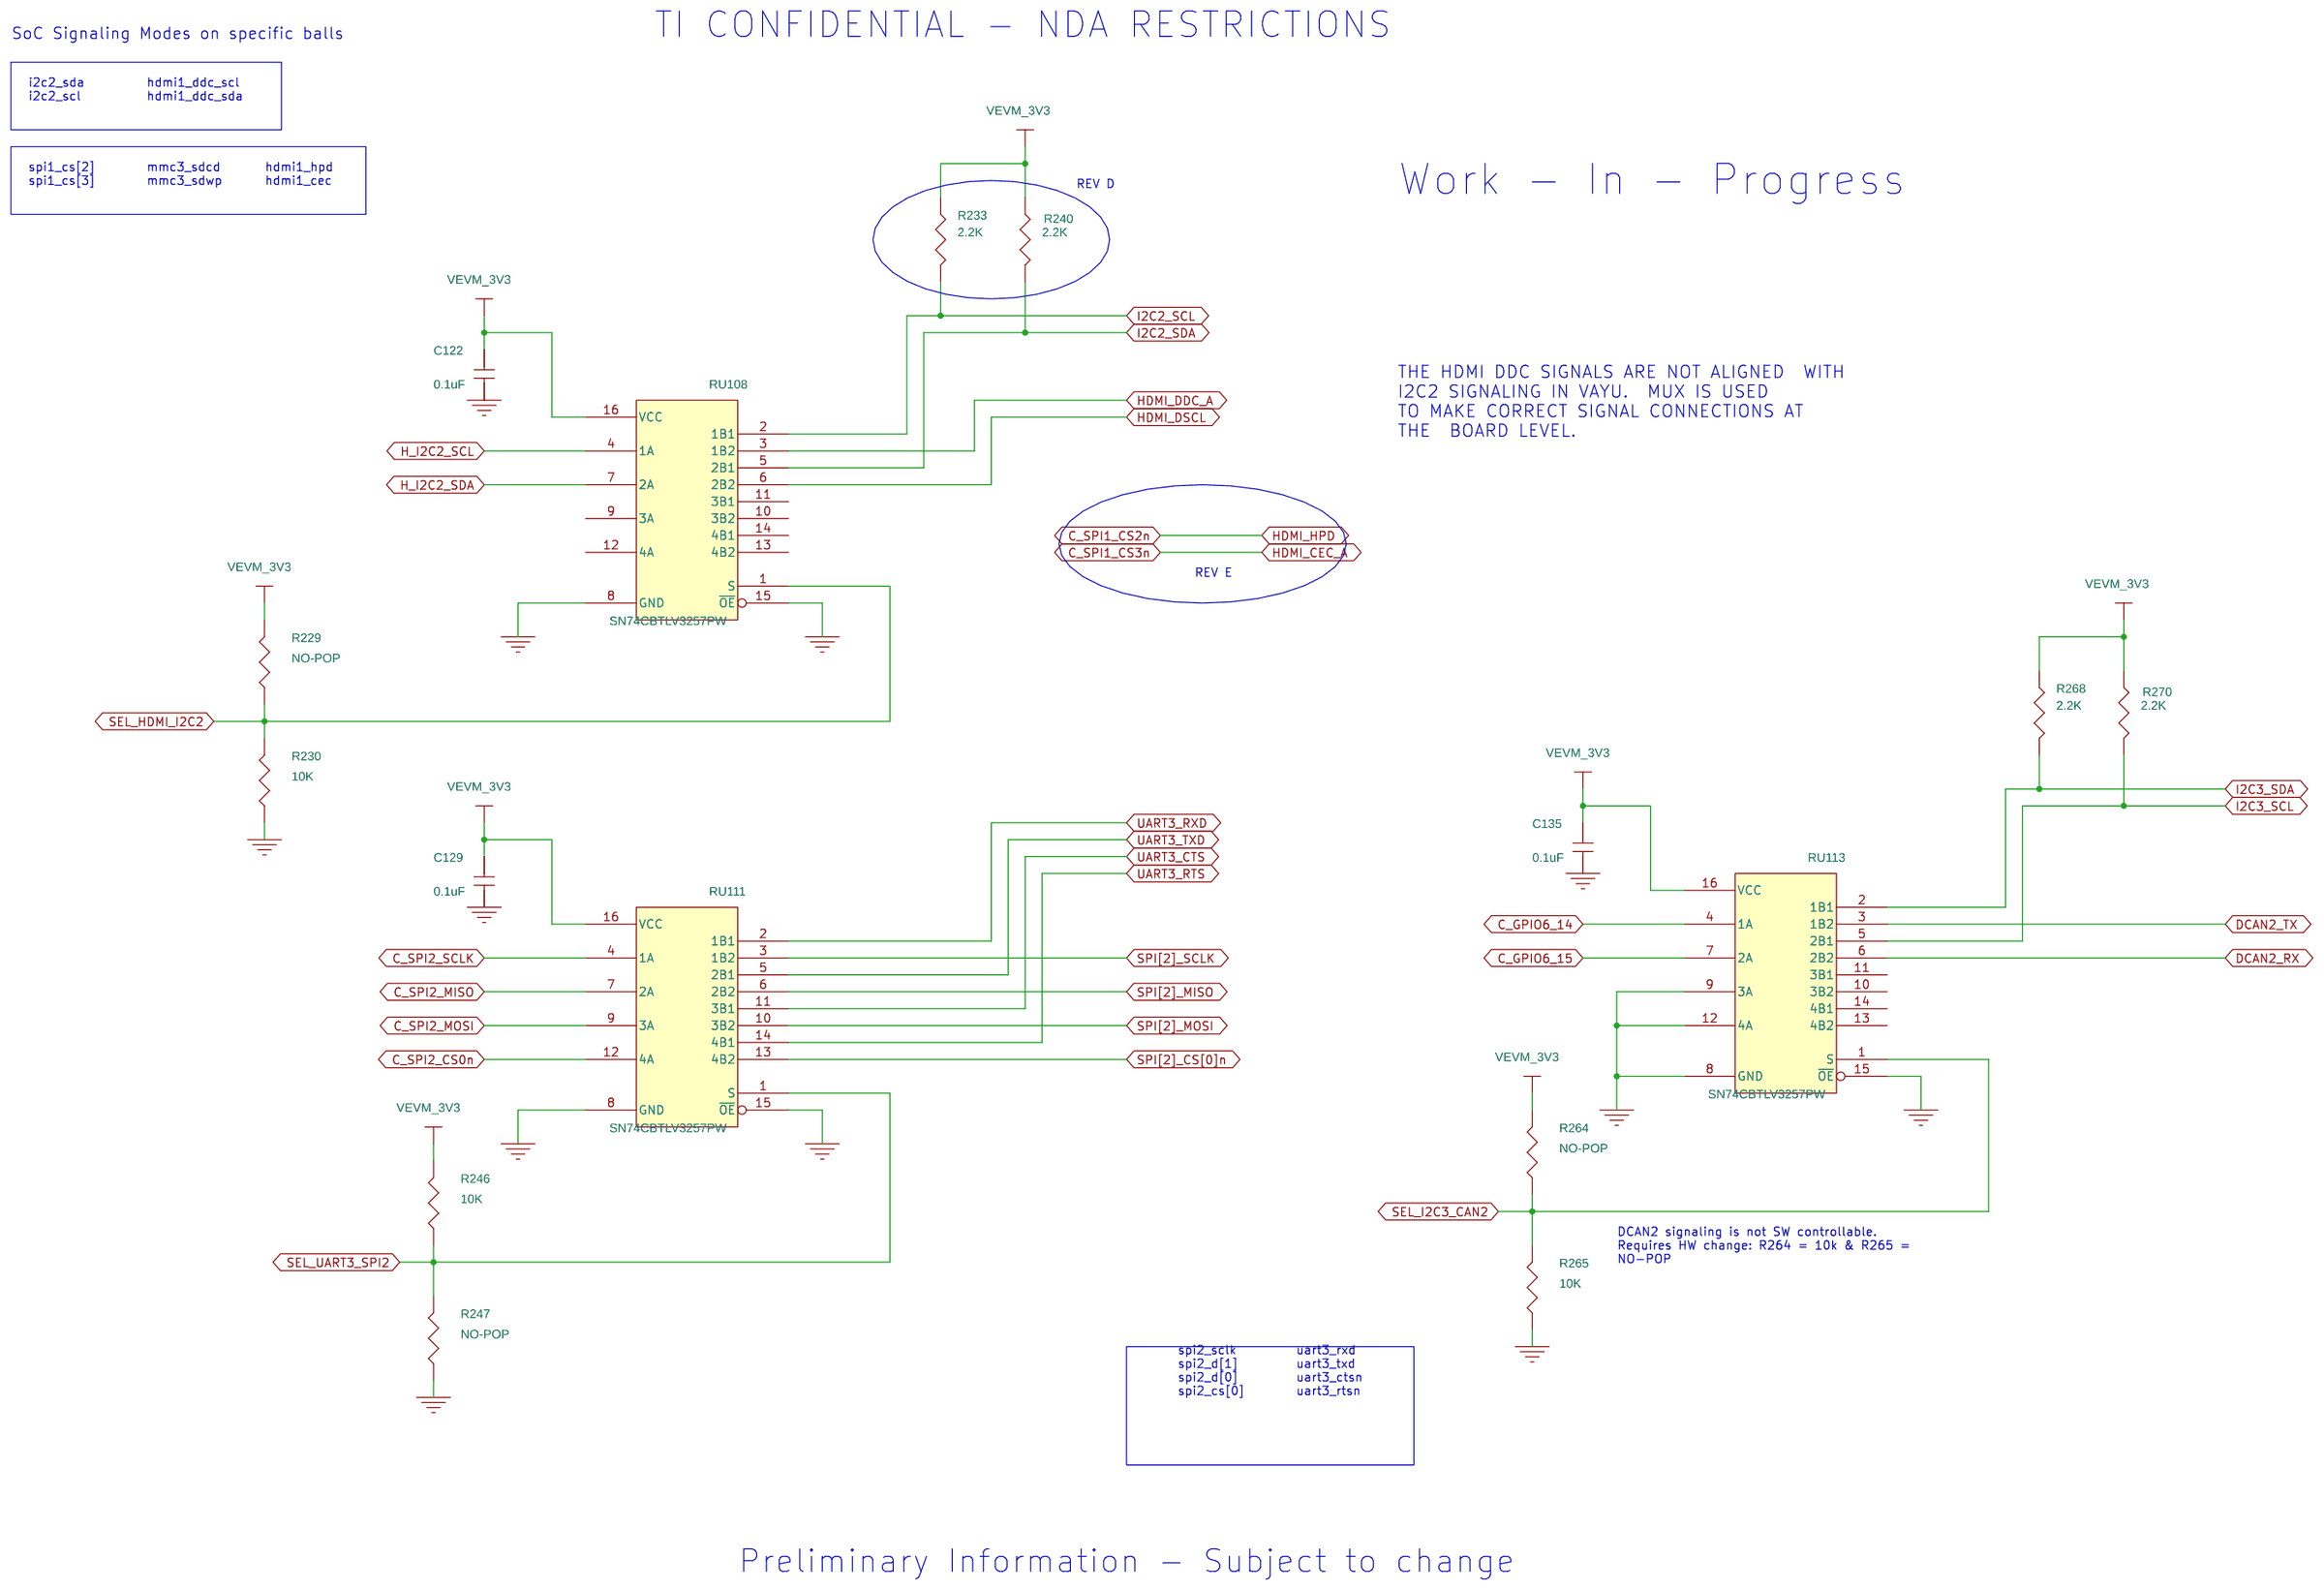
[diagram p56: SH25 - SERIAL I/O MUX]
58 SH11 - VAYU VOUT1/LCD PORT: size B; rev: A
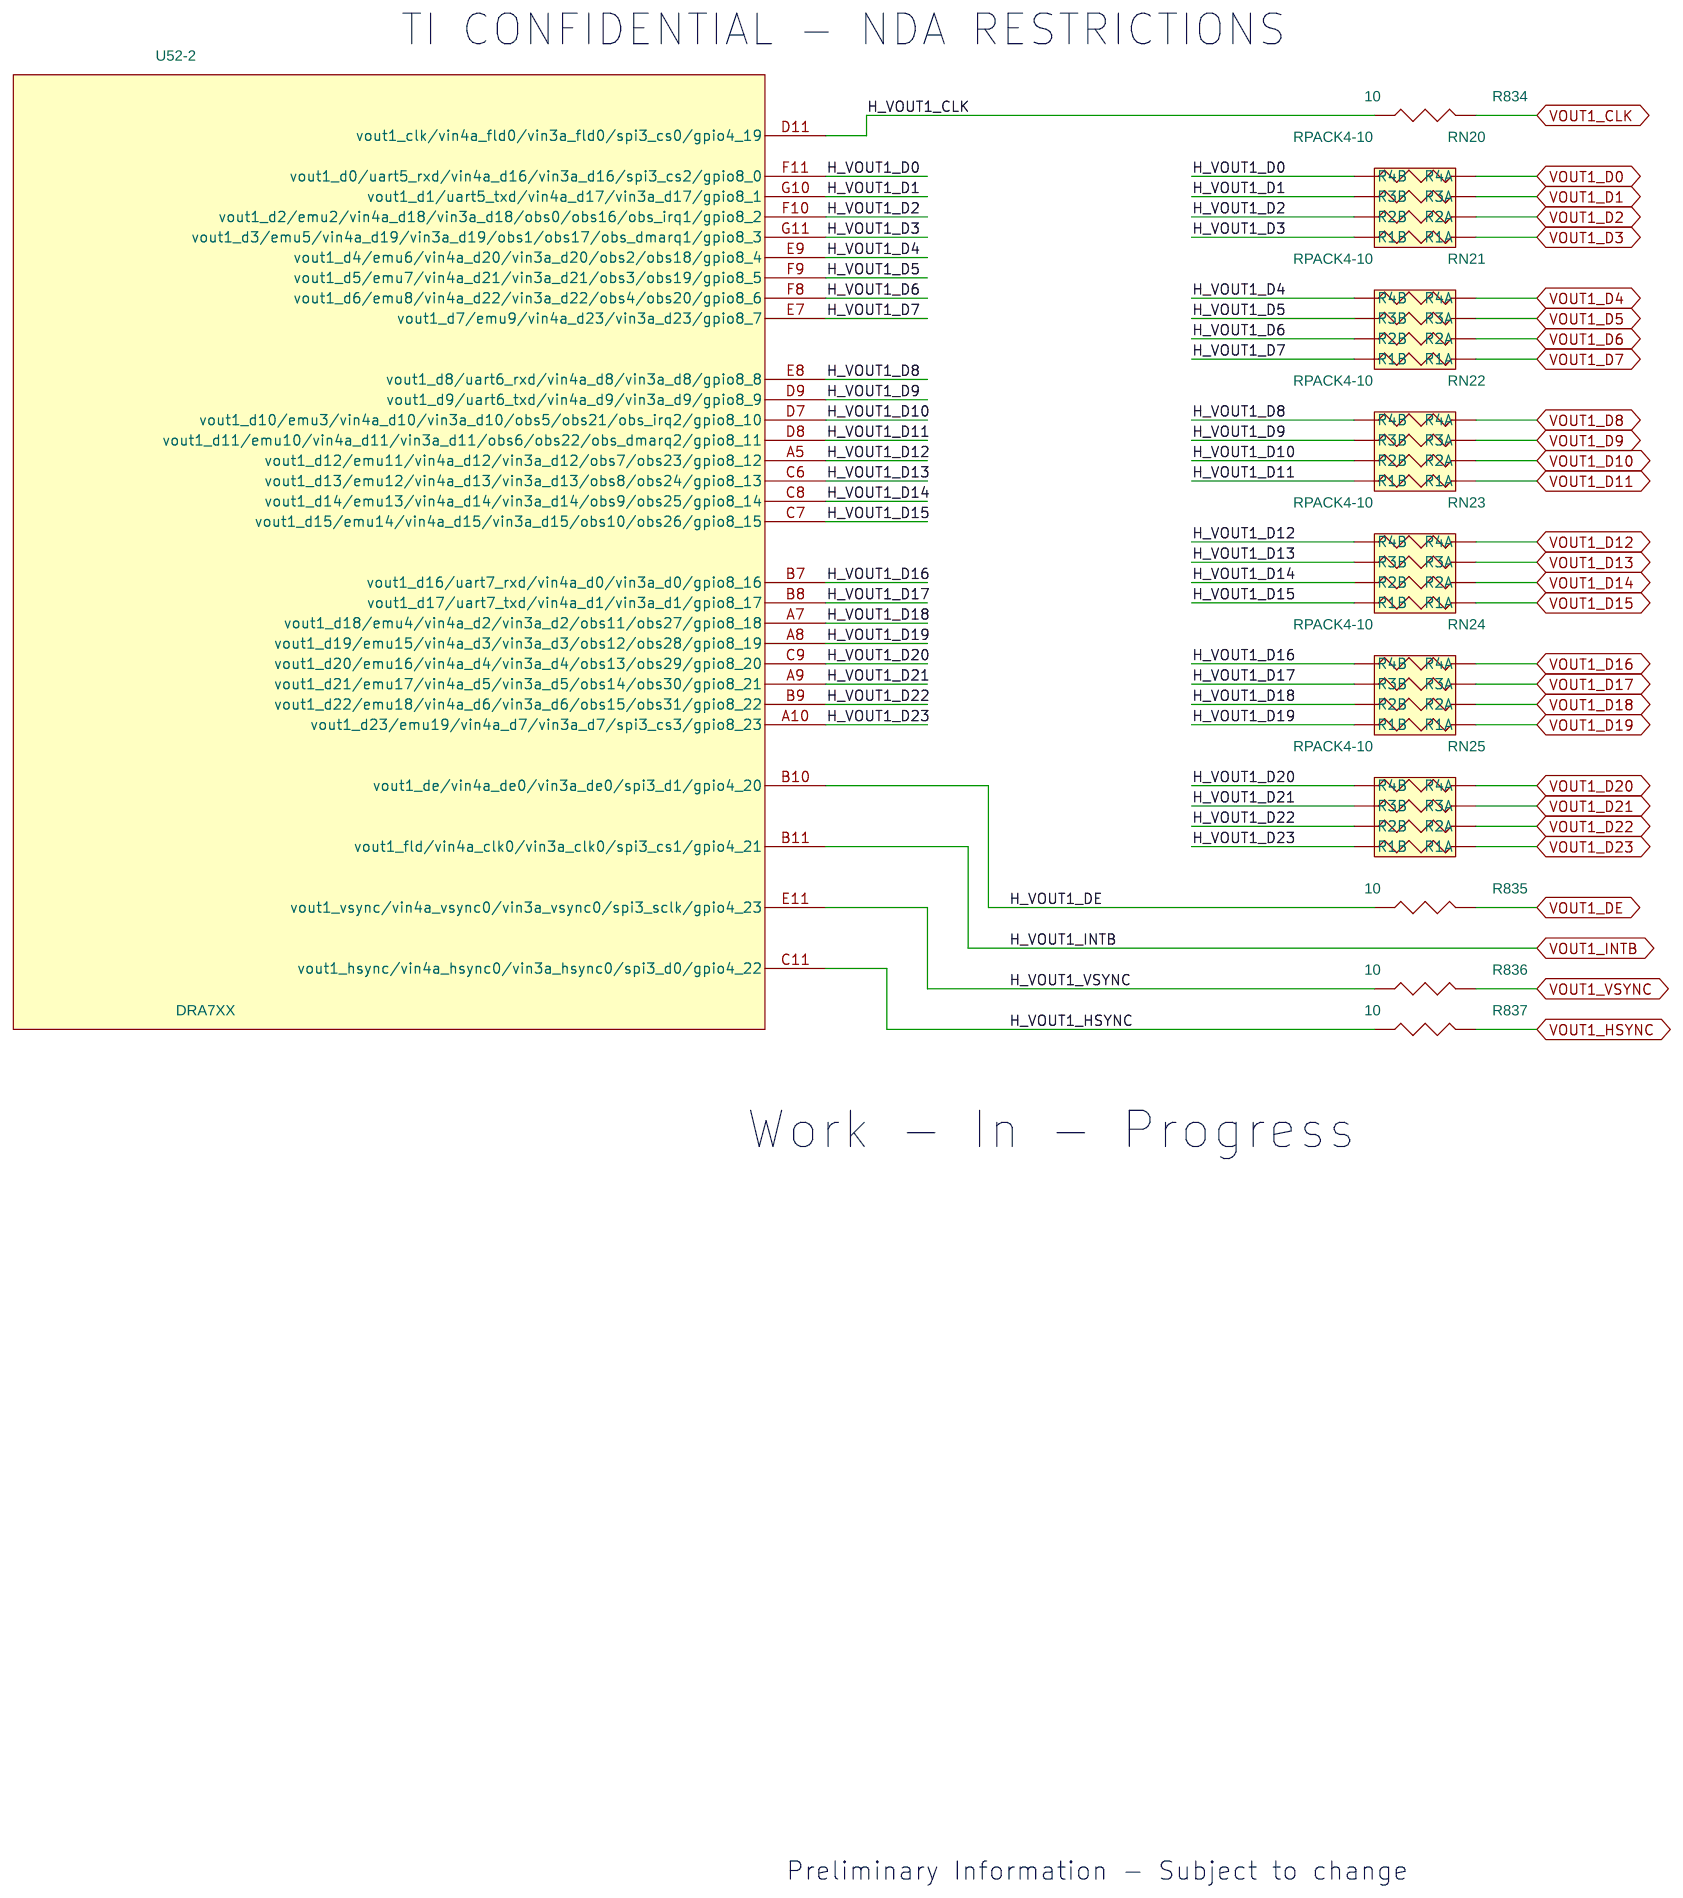
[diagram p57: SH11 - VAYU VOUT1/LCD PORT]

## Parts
sheet SH03 - VAYU SERIAL I/O
R232  10  [r402-25]
R618  2.2K  [r402-25]
R624  2.2K  [r402-25]
R633  2.2K  [r402-25]
R651  10  [r402-25]
R652  2.2K  [r402-25]
R866  2.2K  [r402-25]
R867  2.2K  [r402-25]
sheet SH05 - VAYU ETHERNET
U52  DRA7XX  [bga-zkk-6334-p760]  (sections -1,-10,-11,-12,-13,-14,-15,-16,-17,-18,-19,-2,-20,-21,-22,-23,-3,-4,-5,-6,-7,-8,-9)
sheet SH11 - VAYU VOUT1/LCD PORT
R834  10  [r402-25]
R835  10  [r402-25]
R836  10  [r402-25]
R837  10  [r402-25]
RN20  RPACK4-10  [rpak8-10x25-28v]
RN21  RPACK4-10  [rpak8-10x25-28v]
RN22  RPACK4-10  [rpak8-10x25-28v]
RN23  RPACK4-10  [rpak8-10x25-28v]
RN24  RPACK4-10  [rpak8-10x25-28v]
RN25  RPACK4-10  [rpak8-10x25-28v]
sheet SH25 - SERIAL I/O MUX
C122  0.1uF  [c402-25]
C129  0.1uF  [c402-25]
C135  0.1uF  [c402-25]
R229  NO-POP  [r201-6p6spc]
R230  10K  [r201-6p6spc]
R233  2.2K  [r402-25]
R240  2.2K  [r402-25]
R246  10K  [r201-6p6spc]
R247  NO-POP  [r201-6p6spc]
R264  NO-POP  [r201-6p6spc]
R265  10K  [r201-6p6spc]
R268  2.2K  [r402-25]
R270  2.2K  [r402-25]
RU108  SN74CBTLV3257PW  [tssop16-14x70]
RU111  SN74CBTLV3257PW  [tssop16-14x70]
RU113  SN74CBTLV3257PW  [tssop16-14x70]
sheet SH39 - CAN/LIN
C525  4700pF  [c402-25]
C527  0.1uF  [c402-25]
C531  0.1uF  [c402-25]
C540  0.1uF  [c402-25]
C716  0.1uF  [c402-25]
C720  0.1uF  [c402-25]
C721  0.1uF  [c402-25]
D1  DIODE  [powermite-case457-04]
D2  DIODE  [powermite-case457-04]
R238  62  [r1206-40x70]
R255  62  [r1206-40x70]
R615  10K  [r402-25]
R617  NP  [r402-25]
R830  1K  [r402-25]
R831  10K ???  [r402-25]
R832  10K  [r402-25]
R848  NP  [r402-25]
R849  10K  [r402-25]
R850  0  [r402-25]
R851  0  [r402-25]
R933  0  [r402-25]
R934  NP  [r402-25]
R935  0  [r402-25]
R936  NP  [r402-25]
R937  0  [r402-25]
R938  NP  [r402-25]
R939  NP  [r402-25]
R941  0  [r402-25]
R942  0  [r402-25]
TP76  NP  [tp20]
TP77  NP  [tp20]
U54  HVDA551-Q1  [so8-25x75]
U110  SN74LVC1G04DCK  [dck-5]
U122  SN65HVDA100-Q1  [so8-25x75]
U123  HVDA551-Q1  [so8-25x75]
sheet SH52 - BD POWER 3V3 SWITCHED
C318  220pF 50V  [c603-35x45]
C319  NP  [c603-35x45]
E8  NFM21PC474R1C3D  [emi-NFM21p]
E11  NFM21PC474R1C3D  [emi-NFM21p]
R35  0  [r402-25]
R473  10K  [r402-25]
U92  TPS22965DSG  [dsg8-11x20]
sheet SH53 - BD POWER VTT DDR3 TERM
C174  10uF  [C1206-40X70]
C179  10pF  [c402-25]
C186  1000pF  [c402-25]
C187  0.001uF  [c402-25]
C188  10uF  [C1206-40X70]
C191  10uF  [C1206-40X70]
C192  10uF  [C1206-40X70]
C201  10uF  [C1206-40X70]
C202  10uF  [C1206-40X70]
C607  0.1uF  [c402-25]
C658  0.1uF  [c402-25]
C659  0.1uF  [c402-25]
R282  100K  [r402-25]
R283  10K  [r402-25]
R290  10  [r402-25]
R291  10.0K 1%  [r402-25]
R292  10.0K 1%  [r402-25]
U64  TPS51200  [drc10-11x33]
sheet SH54 - BD POWER 1V35 DDR3 CORE
C149  0.1uF  [c402-25]
C150  NP  [c402-25]
C154  47uF  [C1206-40X70]
C155  4700pF  [c402-25]
C156  10uF  [C1206-40X70]
C157  12pF  [c402-25]
C579  3300pf  [c402-25]
L20  1.2uH (SD12-1R2-R)  [sd12-202x60]
R272  10K  [r402-25]
R273  10K  [r402-25]
R276  NP  [r603-35X45]
R277  86.6K 1%  [r402-25]
R278  16.0K 1%  [r603-35x45]
R279  11.0K 1%  [r402-25]
R280  12k  [r402-25]
TP61  NP  [tp20]
U63  TPS57112QRTERQ1  [rte16-12x34]
sheet SH55 - BD EEPROM TEMP IPOD
C513  0.1uF  [c402-25]
C523  0.1uF  [c402-25]
C733  0.1uF  [c402-25]
C734  10uF  [c603-35x45]
C735  0.1uF  [c402-25]
P5  SFM-105-02-S-D-LC  [conn2x5-amp104652]
R420  0  [r402-25]
R573  NP  [r402-25]
R574  NP  [r402-25]
R575  NP  [r402-25]
R576  0  [r402-25]
R577  NP  [r402-25]
R578  0  [r402-25]
R625  0  [r402-25]
R629  NP  [r402-25]
R864  0  [r402-25]
R865  0  [r402-25]
TP62  NP  [tp20]
TP63  NP  [tp20]
TP64  NP  [tp20]
U105  24WC256  [so8-25x75-295]
U117  TMP102AIDRLT  [drl6-12x30]

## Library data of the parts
R232 R651 R834-R837 = R: Part #: 103158-1000R
R233 R240 R268 R270 R618 R624 R633 R652 R866 R867 = R: Part #: 101370-2202R
U52 = VAYU_DEC_3_2: Part #: 104183-0001R
RN20-RN25 = R-PACK4: Part #: 101327-1000R
C122 C129 C135 C149 C607 C658 C659 C733 C735 = CAP_NP: Part #: 101587-1100R
R229 R247 R264 = R: Part #: R0201-NOPOP
R230 R246 R265 = R: Part #: 103158-1003R
RU108 RU111 RU113 = SN74CBT3257PW: Part #: 101670-0001R
C525 = CAP: Part #: 103217-1472R
C527 C531 C540 C716 C720 C721 = CAP: Part #: 101587-1100R
D1 D2 = DIODE: Part #: 103677-0001R
R238 R255 = R: Part #: 100155-6200R
R272 R273 R283 R615 R831 R832 R849 = R: Part #: 101370-1003R
R573-R575 R577 R617 R629 R848 = R: Part #: R0402-NOPOP
R830 = R: Part #: 101370-1002R
R35 R420 R850 R851 R864 R865 R933 R935 R937 R941 R942 = R: Part #: 101370-0001R
R934 R936 R938 R939 = R: Part #: r0402-nopop
TP62-TP64 TP76 TP77 = TestPoint1_0: Part #: SMT-TP020
U54 U123 = SN65HVDA541: Part #: 104388-0001R
U110 = SN74LVC1GU04_1: Part #: 101057-0004R
U122 = SN65HVDA100-Q1: Part #: 104395-0001R
C318 = CAP: Part #: 100993-1223R
C319 = CAP: Part #: C0603-NOPOP
E8 E11 = NFM_1: Part #: 102569-1470R
R473 = RESISTOR: Part #: 101370-1003R
U92 = TPS22965DSG: Part #: 104267-0001R
C156 C174 C188 C191 C192 C201 C202 = CAP_NP: Part #: 101497-0101R
C179 = CAP_NP: Part #: 101782-1104R
C186 C187 = CAP_NP: Part #: 102058-1102R
R282 = R: Part #: 101370-1004R
R290 = R: Part #: 101370-1000R
R291 R292 = R: Part #: 102145-1003R
U64 = TPS51200: Part #: 103316-0001R
C150 = CAP_NP: Part #: C0402-NOPOP
C154 = CAP_NP: Part #: 101497-0471R
C155 = CAP_NP: Part #: 103217-1472R
C157 = CAP_NP: Part #: 101782-1124R
C579 = CAP_NP: Part #: 102058-1332R
L20 = INDUCTOR: Part #: 103025-0120R
R276 = R: Part #: R0603-NOPOP
R277 = R: Part #: 102145-8663R
R278 = R: Part #: 102145-1603R
R279 = R: Part #: 102145-1103R
R280 = R: Part #: 102145-1203R
TP61 = TESTPOINT: Part #: SMT-TP020
U63 = TPS57112QRTERQ1_0: Part #: 103994-0001R
C513 C523 = CAP_.1_uF_10%_0603: Part #: 101587-1100R
C734 = CAP_NP: Part #: 102963-0101R
P5 = SFM-105-02-S-D-LC_0: Part #: 100562-0005R
R576 R578 R625 = R_1: Part #: 101370-0001R
U105 = 24WC256: Part #: 102235-0001R
U117 = TMP102AIDRLT: Part #: 104192-0001R

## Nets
GND: C122.2 C129.2 C135.2 C154.2 C155.2 C156.2 C157.1 C174.1 C179.1 C186.1 C187.1 C188.1 C191.1 C192.1 C201.1 C202.1 C318.2 C319.2 C513.1 C523.1 C525.2 C527.2 C531.2 C540.2 C579.1 C607.1 C658.1 C659.1 C716.2 C720.2 C721.2 C733.1 C734.1 C735.2 E8.2 E11.2 P5.9 P5.10 R230.2 R247.2 R265.2 R273.1 R276.1 R277.1 R278.1 R291.1 R473.2 R574.2 R576.2 R578.2 R615.2 R617.2 R625.2 R832.2 R848.2 R849.2 RU108.8(GND) RU108.15(~{OE}) RU111.8(GND) RU111.15(~{OE}) RU113.8(GND) RU113.9(3A) RU113.12(4A) RU113.15(~{OE}) U54.2(GND) U63.3(GND.1) U63.4(GND.2) U63.5(AGND) U63.17(PwrPad) U64.4(PGND) U64.8(GND) U64.11(PWRPAD) U92.5(GND) U92.9(PWR_PAD) U105.4(VSS) U110.3(GND) U117.2(GND) U122.5(GND) U123.2(GND) ; also on sheet 3 5 7 8 9 11 12 13 14 15 16 17 18 19 20 21 22 24 25 28 29 31 32 33 34 35 36 37 38 39 40 41 42 43 44 45 46 47 48
VDD_DCDC_DDR_1V35: C154.1 L20.2 R279.2
VDD_DDR: C187.2 C191.2 C201.2 C659.2 R292.2 U64.2(VLDOIN) ; also on sheet 17 24 25 26 28 29 30 42
VDDR_VREFSTL: C607.2 U64.6(REFOUT) ; also on sheet 7 8 24 28
VDDSHV: E11.3 ; also on sheet 15
VDDSHV5: C527.1 C540.1 U54.5(VIO/NC) U110.5(VCC) ; also on sheet 13 41 44
C_GPIO6_14: RU113.4(1A)
C_GPIO6_15: RU113.7(2A)
C_SPI2_CS0n: RU111.12(4A)
C_SPI2_MISO: RU111.7(2A)
C_SPI2_MOSI: RU111.9(3A)
C_SPI2_SCLK: RU111.4(1A)
DCAN1_RX: U54.4(RXD)
DCAN1_TX: R617.1 U54.1(TXD)
DCAN2_RX: RU113.6(2B2)
DCAN2_TX: RU113.3(1B2)
EVM_12V: D1.2(A)
H_DCAN1_RX: R232.2 U52.G19(dcan1_rx/uart8_txd/mmc2_sdwp/sata1_led/hdmi1_cec/gpio1_15)
H_DCAN1_TX: U52.G20(dcan1_tx/uart8_rxd/mmc2_sdcd/hdmi1_hpd/gpio1_14)
H_GPIO1_15_WAKEUP_CAN: R232.1
H_GPIO5_18: U52.V2(uart3_rxd/rmii1_crs/mii0_rxdv/vin2a_d1/vin4b_d1/spi3_sclk/gpio5_18)
H_GPIO5_19: U52.Y1(uart3_txd/rmii1_rxer/mii0_rxclk/vin2a_d2/vin4b_d2/spi3_d1/spi4_cs1/gpio5_19)
H_GPIO6_10: U52.AC5(gpio6_10/mdio_mclk/i2c3_sda/usb3_ulpi_d7/vin2b_hsync1/vin5a_clk0/ehrpwm2A)
H_GPIO6_11: U52.AB4(gpio6_11/mdio_d/i2c3_scl/usb3_ulpi_d6/vin2b_vsync1/vin5a_de0/ehrpwm2B)
H_GPIO6_16: U52.F21(gpio6_16/mcasp1_axr10/vout2_fld/vin4a_fld0/clkout1/timer3)
H_GPIO7_7: U52.A25(spi1_sclk/gpio7_7)
H_GPIO7_8: U52.F16(spi1_d1/gpio7_8)
H_GPIO7_9: U52.B25(spi1_d0/gpio7_9)
H_GPIO7_10: U52.A24(spi1_cs0/gpio7_10)
H_GPIO7_11: U52.A22(spi1_cs1/sata1_led/spi2_cs1/gpio7_11)
H_I2C1_SCL: R618.2 R624.2 U52.C20(i2c1_scl) U52.C21(i2c1_sda)
H_I2C2_SCL: R633.2 R652.2 RU108.4(1A) U52.C25(i2c2_sda/hdmi1_ddc_scl) U52.F17(i2c2_scl/hdmi1_ddc_sda)
H_I2C2_SDA: RU108.7(2A)
H_I2C3_SCL: R866.1 U52.F20(gpio6_15/mcasp1_axr9/dcan2_rx/uart10_txd/vout2_vsync/vin4a_vsync0/i2c3_scl/timer2)
H_I2C3_SDA: R867.1 U52.E21(gpio6_14/mcasp1_axr8/dcan2_tx/uart10_rxd/vout2_hsync/vin4a_hsync0/i2c3_sda/timer1)
H_MMC4_CLK: R651.2 U52.E25(uart1_ctsn/uart9_rxd/mmc4_clk/gpio7_24)
H_MMC4_CLK_S1: R651.1
H_MMC4_CMD: U52.C27(uart1_rtsn/uart9_txd/mmc4_cmd/gpio7_25)
H_MMC4_DAT0: U52.D28(uart2_rxd/uart3_ctsn/uart3_rctx/mmc4_dat0/uart2_rxd/uart1_dcdn/gpio7_26)
H_MMC4_DAT1: U52.D26(uart2_txd/uart3_rtsn/uart3_sd/mmc4_dat1/uart2_txd/uart1_dsrn/gpio7_27)
H_MMC4_DAT2: U52.D27(uart2_ctsn/uart3_irrx/mmc4_dat2/uart10_rxd/uart1_dtrn/gpio1_16)
H_MMC4_DAT3: U52.C28(uart2_rtsn/uart3_txd/uart3_irtx/mmc4_dat3/uart10_txd/uart1_rin/gpio1_17)
H_RSTOUT_N: R864.1 ; also on sheet 13 21 22 38 39 46
H_UART1_DBG_RX1: U52.B27(uart1_rxd/mmc4_sdcd/gpio7_22)
H_UART1_DBG_TX1: U52.C26(uart1_txd/mmc4_sdwp/gpio7_23)
H_UART3_CTS: U52.G17(spi2_d0/uart3_ctsn/uart5_rxd/gpio7_16)
H_UART3_RTS: U52.B24(spi2_cs0/uart3_rtsn/uart5_txd/gpio7_17)
H_UART3_RXD: U52.A26(spi2_sclk/uart3_rxd/gpio7_14)
H_UART3_TXD: U52.B22(spi2_d1/uart3_txd/gpio7_15)
H_UART4_LIN_RXD: U52.B21(spi1_cs2/uart4_rxd/mmc3_sdcd/spi2_cs2/dcan2_tx/mdio_mclk/hdmi1_hpd/gpio7_12)
H_UART4_LIN_TXD: U52.B20(spi1_cs3/uart4_txd/mmc3_sdwp/spi2_cs3/dcan2_rx/mdio_d/hdmi1_cec/gpio7_13)
H_VOUT1_CLK: R834.2 U52.D11(vout1_clk/vin4a_fld0/vin3a_fld0/spi3_cs0/gpio4_19)
H_VOUT1_D0: RN20.5(R4B) U52.F11(vout1_d0/uart5_rxd/vin4a_d16/vin3a_d16/spi3_cs2/gpio8_0)
H_VOUT1_D1: RN20.6(R3B) U52.G10(vout1_d1/uart5_txd/vin4a_d17/vin3a_d17/gpio8_1)
H_VOUT1_D2: RN20.7(R2B) U52.F10(vout1_d2/emu2/vin4a_d18/vin3a_d18/obs0/obs16/obs_irq1/gpio8_2)
H_VOUT1_D3: RN20.8(R1B) U52.G11(vout1_d3/emu5/vin4a_d19/vin3a_d19/obs1/obs17/obs_dmarq1/gpio8_3)
H_VOUT1_D4: RN21.5(R4B) U52.E9(vout1_d4/emu6/vin4a_d20/vin3a_d20/obs2/obs18/gpio8_4)
H_VOUT1_D5: RN21.6(R3B) U52.F9(vout1_d5/emu7/vin4a_d21/vin3a_d21/obs3/obs19/gpio8_5)
H_VOUT1_D6: RN21.7(R2B) U52.F8(vout1_d6/emu8/vin4a_d22/vin3a_d22/obs4/obs20/gpio8_6)
H_VOUT1_D7: RN21.8(R1B) U52.E7(vout1_d7/emu9/vin4a_d23/vin3a_d23/gpio8_7)
H_VOUT1_D8: RN22.5(R4B) U52.E8(vout1_d8/uart6_rxd/vin4a_d8/vin3a_d8/gpio8_8)
H_VOUT1_D9: RN22.6(R3B) U52.D9(vout1_d9/uart6_txd/vin4a_d9/vin3a_d9/gpio8_9)
H_VOUT1_D10: RN22.7(R2B) U52.D7(vout1_d10/emu3/vin4a_d10/vin3a_d10/obs5/obs21/obs_irq2/gpio8_10)
H_VOUT1_D11: RN22.8(R1B) U52.D8(vout1_d11/emu10/vin4a_d11/vin3a_d11/obs6/obs22/obs_dmarq2/gpio8_11)
H_VOUT1_D12: RN23.5(R4B) U52.A5(vout1_d12/emu11/vin4a_d12/vin3a_d12/obs7/obs23/gpio8_12)
H_VOUT1_D13: RN23.6(R3B) U52.C6(vout1_d13/emu12/vin4a_d13/vin3a_d13/obs8/obs24/gpio8_13)
H_VOUT1_D14: RN23.7(R2B) U52.C8(vout1_d14/emu13/vin4a_d14/vin3a_d14/obs9/obs25/gpio8_14)
H_VOUT1_D15: RN23.8(R1B) U52.C7(vout1_d15/emu14/vin4a_d15/vin3a_d15/obs10/obs26/gpio8_15)
H_VOUT1_D16: RN24.5(R4B) U52.B7(vout1_d16/uart7_rxd/vin4a_d0/vin3a_d0/gpio8_16)
H_VOUT1_D17: RN24.6(R3B) U52.B8(vout1_d17/uart7_txd/vin4a_d1/vin3a_d1/gpio8_17)
H_VOUT1_D18: RN24.7(R2B) U52.A7(vout1_d18/emu4/vin4a_d2/vin3a_d2/obs11/obs27/gpio8_18)
H_VOUT1_D19: RN24.8(R1B) U52.A8(vout1_d19/emu15/vin4a_d3/vin3a_d3/obs12/obs28/gpio8_19)
H_VOUT1_D20: RN25.5(R4B) U52.C9(vout1_d20/emu16/vin4a_d4/vin3a_d4/obs13/obs29/gpio8_20)
H_VOUT1_D21: RN25.6(R3B) U52.A9(vout1_d21/emu17/vin4a_d5/vin3a_d5/obs14/obs30/gpio8_21)
H_VOUT1_D22: RN25.7(R2B) U52.B9(vout1_d22/emu18/vin4a_d6/vin3a_d6/obs15/obs31/gpio8_22)
H_VOUT1_D23: RN25.8(R1B) U52.A10(vout1_d23/emu19/vin4a_d7/vin3a_d7/spi3_cs3/gpio8_23)
H_VOUT1_DE: R835.2 U52.B10(vout1_de/vin4a_de0/vin3a_de0/spi3_d1/gpio4_20)
H_VOUT1_HSYNC: R837.2 U52.C11(vout1_hsync/vin4a_hsync0/vin3a_hsync0/spi3_d0/gpio4_22)
H_VOUT1_VSYNC: R836.2 U52.E11(vout1_vsync/vin4a_vsync0/vin3a_vsync0/spi3_sclk/gpio4_23)
HDMI_DDC_A: RU108.3(1B2)
HDMI_DSCL: RU108.6(2B2)
HSGMLAN_BUS+: R238.1 R850.1 R941.1
HSGMLAN_BUS-: R255.2 R851.1 R942.1
I2C1_SCL: U105.6(SCL) U117.1(SCL) ; also on sheet 35 39
I2C1_SDA: U105.5(SDA) U117.6(SDA) ; also on sheet 35 39
I2C2_SCL: R233.2 RU108.2(1B1) ; also on sheet 37 38
I2C2_SDA: R240.2 RU108.5(2B1) ; also on sheet 37 38
I2C3_SCL: R270.2 R865.1 RU113.5(2B1)
I2C3_SDA: R268.2 R420.2 RU113.2(1B1)
I2C_EEPROM_WP: U105.7(WP) ; also on sheet 45
LIN_EN: R935.2
LIN_INH: TP76.1 U122.8(INH)
LIN_WAKE: TP77.1 U122.3(NWake)
MCU_DCAN_RX: U123.4(RXD)
MCU_DCAN_STB: R849.1 U123.8(STB)
MCU_DCAN_TX: R848.1 U123.1(TXD)
MCU_LIN_EN: R936.2
MCU_LIN_RXD: R934.2
MCU_LIN_TXD: R938.2
PMIC_GPIO_4_6: R473.1 U92.3(ON) ; also on sheet 40
PMIC_GPIO_6_4: R273.2 U63.15(EN) ; also on sheet 40
PMIC_OFF: U110.2(I) ; also on sheet 13 40
SEL_HDMI_I2C2: R229.2 R230.1 RU108.1(S)
SEL_I2C3_CAN2: R264.2 R265.1 RU113.1(S)
SEL_UART3_SPI2: R246.2 R247.1 RU111.1(S)
SPI[2]_CS[0]n: RU111.13(4B2)
SPI[2]_MISO: RU111.6(2B2)
SPI[2]_MOSI: RU111.10(3B2)
SPI[2]_SCLK: RU111.3(1B2)
TLIN1: R830.2 U122.6(LIN)
UART3_CTS: RU111.11(3B1) ; also on sheet 34
UART3_RTS: RU111.14(4B1) ; also on sheet 34
UART3_RXD: RU111.2(1B1) ; also on sheet 34
UART3_TXD: RU111.5(2B1) ; also on sheet 34
UART4_LIN_RXD: R933.2
UART4_LIN_TXD: R937.2
VDAC_3V3: E8.3 ; also on sheet 39
VEVM_3V3: C122.1 C129.1 C135.1 C156.1 C513.2 C523.2 C733.2 C734.2 P5.1 P5.2 R229.1 R233.1 R240.1 R246.1 R264.1 R268.1 R270.1 R272.1 R573.1 R575.1 R577.1 R618.1 R624.1 R629.1 R633.1 R652.1 R831.1 R866.2 R867.2 RU108.16(VCC) RU111.16(VCC) RU113.16(VCC) U63.1(VIN.2) U63.2(VIN.3) U63.16(VIN.1) U92.1(VIN.1) U92.2(VIN.2) U105.8(VCC) U117.5(V+) ; also on sheet 3 12 13 21 22 31 32 33 34 35 37 38 40 41 42 43 44 45 46 48
VEVM_3V3_SW: C174.2 C319.1 E8.1 E11.1 R282.2 R283.2 U64.10(VIN) U92.7(VOUT.2) U92.8(VOUT.1)
VEVM_5V0: C531.1 C720.1 R35.1 U54.3(VCC) U123.3(VCC) ; also on sheet 31 32 33 36 41 48
VMCU_3V3: C721.1 R939.1 U123.5(VIO/NC) ; also on sheet 46
VOUT1_CLK: R834.1 ; also on sheet 37
VOUT1_D0: RN20.4(R4A) ; also on sheet 37
VOUT1_D1: RN20.3(R3A) ; also on sheet 37
VOUT1_D2: RN20.2(R2A) ; also on sheet 12 37
VOUT1_D3: RN20.1(R1A) ; also on sheet 12 37
VOUT1_D4: RN21.4(R4A) ; also on sheet 12 37
VOUT1_D5: RN21.3(R3A) ; also on sheet 12 37
VOUT1_D6: RN21.2(R2A) ; also on sheet 12 37
VOUT1_D7: RN21.1(R1A)
VOUT1_D8: RN22.4(R4A) ; also on sheet 37
VOUT1_D9: RN22.3(R3A) ; also on sheet 37
VOUT1_D10: RN22.2(R2A) ; also on sheet 12 37
VOUT1_D11: RN22.1(R1A) ; also on sheet 12 37
VOUT1_D12: RN23.4(R4A) ; also on sheet 12 37
VOUT1_D13: RN23.3(R3A) ; also on sheet 12 37
VOUT1_D14: RN23.2(R2A) ; also on sheet 12 37
VOUT1_D15: RN23.1(R1A) ; also on sheet 12 37
VOUT1_D16: RN24.4(R4A) ; also on sheet 37
VOUT1_D17: RN24.3(R3A) ; also on sheet 37
VOUT1_D18: RN24.2(R2A) ; also on sheet 12 37
VOUT1_D19: RN24.1(R1A) ; also on sheet 12 37
VOUT1_D20: RN25.4(R4A) ; also on sheet 12 37
VOUT1_D21: RN25.3(R3A) ; also on sheet 12 37
VOUT1_D22: RN25.2(R2A) ; also on sheet 12 37
VOUT1_D23: RN25.1(R1A) ; also on sheet 12 37
VOUT1_DE: R835.1 ; also on sheet 37
VOUT1_HSYNC: R837.1 ; also on sheet 37
VOUT1_INTB: U52.B11(vout1_fld/vin4a_clk0/vin3a_clk0/spi3_cs1/gpio4_21) ; also on sheet 37
VOUT1_VSYNC: R836.1 ; also on sheet 37
VTT_DDR: C188.2 C192.2 C202.2 C658.2 R290.2 U64.3(VO) ; also on sheet 26 30
N17444583: C186.2 R291.2 R292.1 U64.1(REFIN)
N17444631: R282.1 U64.9(PGOOD)
N17444633: C179.2 R290.1 U64.5(VOSNS)
N17444649: R283.1 U64.7(EN)
N17681908: R35.2 U92.4(VBIAS)
N18740603: C157.2 R280.1 U63.7(COMP)
N18740978: R278.2 R279.1 U63.6(VSNS)
N18743331: C149.2 U63.13(BOOT)
N18763016: R277.2 U63.8(RT/CLK)
N18763017: C155.1 U63.9(SS/TR)
N18763019: C149.1 C150.1 L20.1 U63.10(PH.1) U63.11(PH.2) U63.12(PH.3)
N18763021: R272.2 TP61.1(TP) U63.14(PWRGD)
N19176689: C579.2 R280.2
N19176787: C150.2 R276.2
N21358273: C525.1 R238.2 R255.1
N21358507: R615.1 U54.8(STB) U110.4(O)
N21553860: R937.1 R938.1 U122.4(TXD)
N21553866: R832.1 R935.1 R936.1 U122.2(EN)
N21553869: R831.2 R933.1 R934.1 R939.2 U122.1(RXD)
N21553972: D2.1(K) R830.1
N21553975: C716.1 D1.1(K) D2.2(A) U122.7(Vsup)
N21759370: R850.2 U123.7(CANH)
N21759373: R851.2 U123.6(CANL)
N21910555: C735.1 P5.4 R864.2
N21910572: P5.6 TP62.1
N21910578: P5.3 TP63.1
N21910586: P5.8 R865.2
N21910590: P5.7 R420.1
N21910592: P5.5 TP64.1
N22823202: R942.2 U54.6(CANL)
N22823205: R941.2 U54.7(CANH)
N29597106: R577.2 R578.1 U105.1(A0)
N29597110: R575.2 R576.1 U105.2(A1)
N29597116: R573.2 R574.1 U105.3(NC)
N29675465: R625.1 R629.2 U117.4(ADD0)
N46501256: C318.1 U92.6(CT)

Not connected (* = marked no-connect by the designer): RU108 9(3A) 10(3B2) 11(3B1) 12(4A) 13(4B2) 14(4B1); RU113 10(3B2) 11(3B1) 13(4B2) 14(4B1); U110 1(NC1); U117 3(ALERT)*

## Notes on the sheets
sheet 49
- TI CONFIDENTIAL - NDA RESTRICTIONS
- Work - In - Progress
- 1.2 volt input
- Preliminary Information - Subject to change
sheet 50
- TI CONFIDENTIAL - NDA RESTRICTIONS
- Work - In - Progress
- Preliminary Information - Subject to change
sheet 51
- TI CONFIDENTIAL - NDA RESTRICTIONS
- Work - In - Progress
- ENABLE VOLTAGE 1.2 VOLTS
- PMIC TRI-STATES GPIO ON
  STARTUP SO KEEP THE DDR3
  SUPPLY DISABLED UNTIL
  DRIVEN.
- Preliminary Information - Subject to change
sheet 52
- TI CONFIDENTIAL - NDA RESTRICTIONS
- Work - In - Progress
- P5 to iPod device via USB
  port (copied from JAMR3)
- Preliminary Information - Subject to change
- Preliminary Information - Subject to change
sheet 53
- TI CONFIDENTIAL - NDA RESTRICTIONS
- PCB Matched Group = H_QSPI_xxx
- PCB Matched Group = H_MMC1_xxx
- Mode = SCK for single commands
  Max Clk = 133MHz
  Mode = SCK for dual & quad commands
  Max Clk = 104MHz
- Mode = SDR104
  Max Clk = 192MHz
  Max Data = 96Mbps
- Work - In - Progress
- See DRA75x_74x Data Manual, Section 8.4.2
  QSPI Board Design & Layout Guidelines
- PCB Matched Group = H_MMC2_xxx
- Mode = HS200
  Max Clk = 192MHz
  Max Data = 96Mbps
- Preliminary Information - Subject to change
sheet 54
- Rev
- Date
- Author
- Notes
- B
- 12/10/2013
- Bill McCracken
- Reduced Dcaps on VDD_CORE, VDD_MPU, VDD_DDR & VDD_DSPEVE_IVA_GPU power rails to align with Power Integrity modelnig results for optimizing Dcap Schemes.
- TI CONFIDENTIAL - NDA RESTRICTIONS
- Work - In - Progress
- Preliminary Information - Subject to change
sheet 55
- TI CONFIDENTIAL - NDA RESTRICTIONS
- Work - In - Progress
- MCU OR VAYU LIN SUPPORT AS
  POPULATION OPTION
- VERIFY DIODE RATINGS
- Preliminary Information - Subject to change
sheet 56
- TI CONFIDENTIAL - NDA RESTRICTIONS
- Work - In - Progress
- Preliminary Information - Subject to change
sheet 57
- TI CONFIDENTIAL - NDA RESTRICTIONS
- SoC Signaling Modes on specific balls
- i2c2_sda
  i2c2_scl
- hdmi1_ddc_scl
  hdmi1_ddc_sda
- spi1_cs[2]
  spi1_cs[3]
- mmc3_sdcd
  mmc3_sdwp
- hdmi1_hpd
  hdmi1_cec
- Work - In - Progress
- REV D
- THE HDMI DDC SIGNALS ARE NOT ALIGNED  WITH
  I2C2 SIGNALING IN VAYU.  MUX IS USED
  TO MAKE CORRECT SIGNAL CONNECTIONS AT
  THE  BOARD LEVEL.
- REV E
- DCAN2 signaling is not SW controllable.
  Requires HW change: R264 = 10k & R265 =
  NO-POP
- spi2_sclk
  spi2_d[1]
  spi2_d[0]
  spi2_cs[0]
- uart3_rxd
  uart3_txd
  uart3_ctsn
  uart3_rtsn
- Preliminary Information - Subject to change
sheet 58
- TI CONFIDENTIAL - NDA RESTRICTIONS
- Work - In - Progress
- Preliminary Information - Subject to change
